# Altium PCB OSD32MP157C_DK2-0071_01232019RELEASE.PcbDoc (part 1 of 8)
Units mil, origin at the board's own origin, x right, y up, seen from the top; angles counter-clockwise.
Board outline 3976.38 x 2795.28 mil, 6 copper layers (Top Layer, Signal Layer 1, Signal Layer 2, Signal Layer 3, Signal Layer 4, Bottom Layer), stack 61.268 mil thick; 404 components, 418 nets, 1720 pads, 1233 vias.
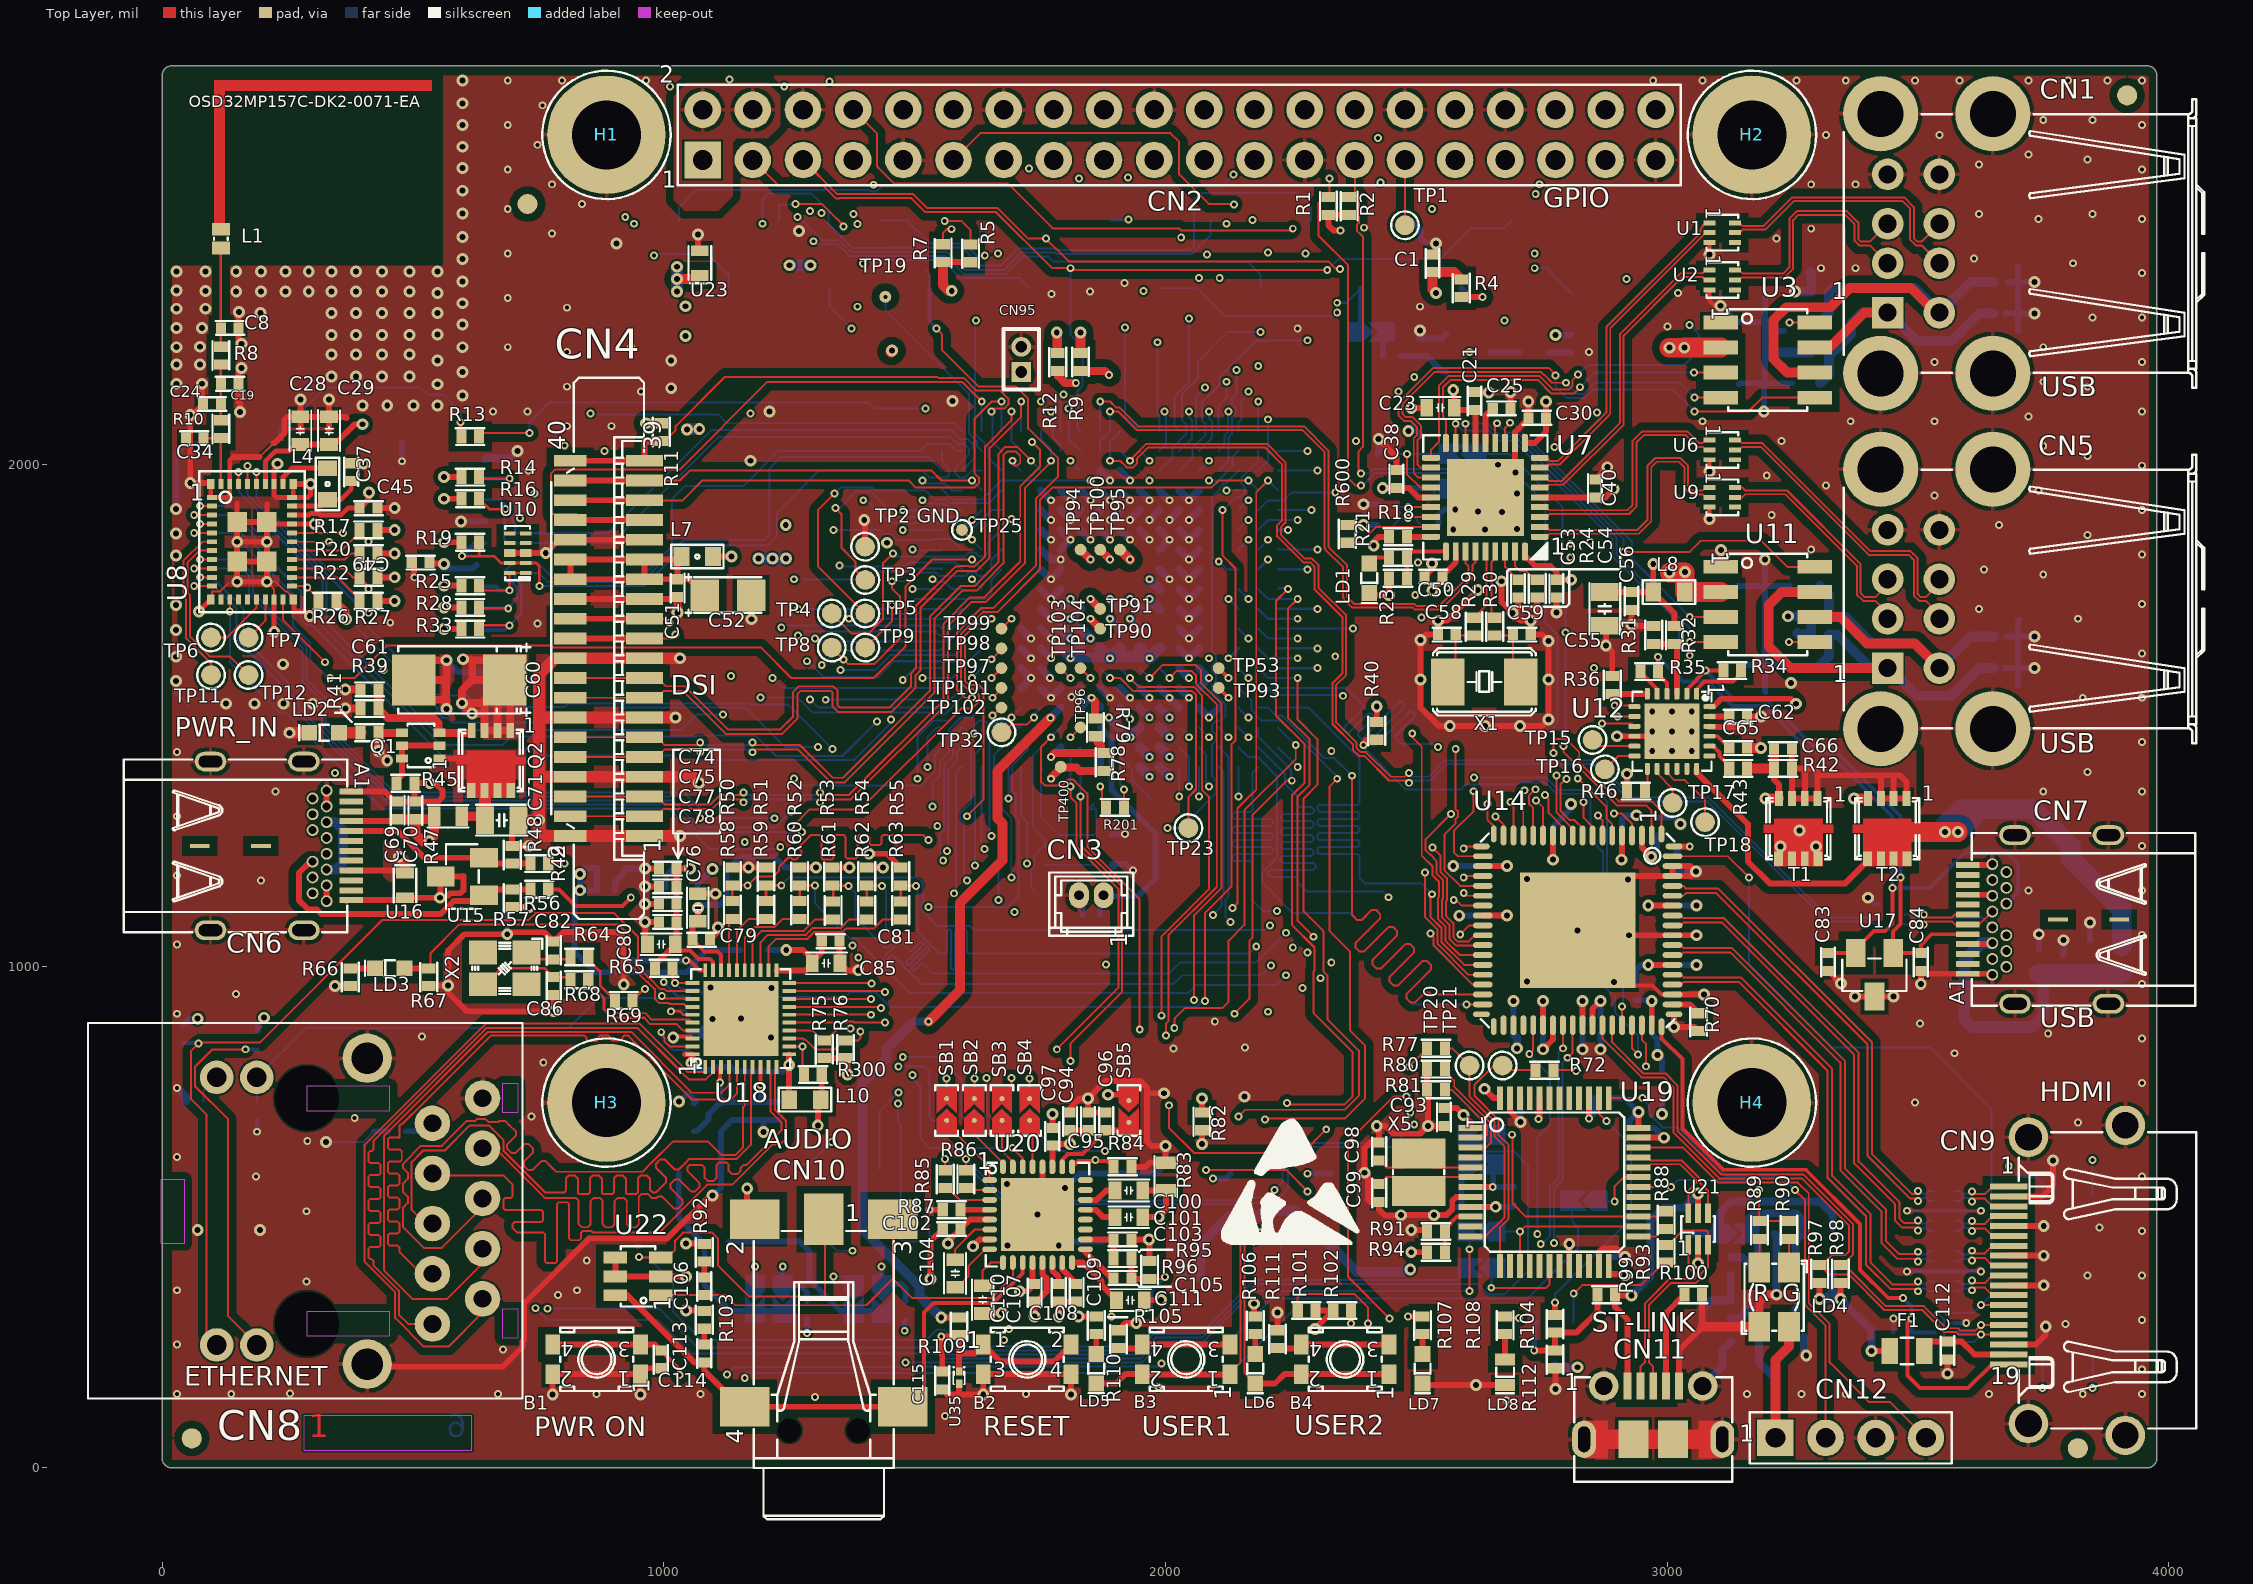
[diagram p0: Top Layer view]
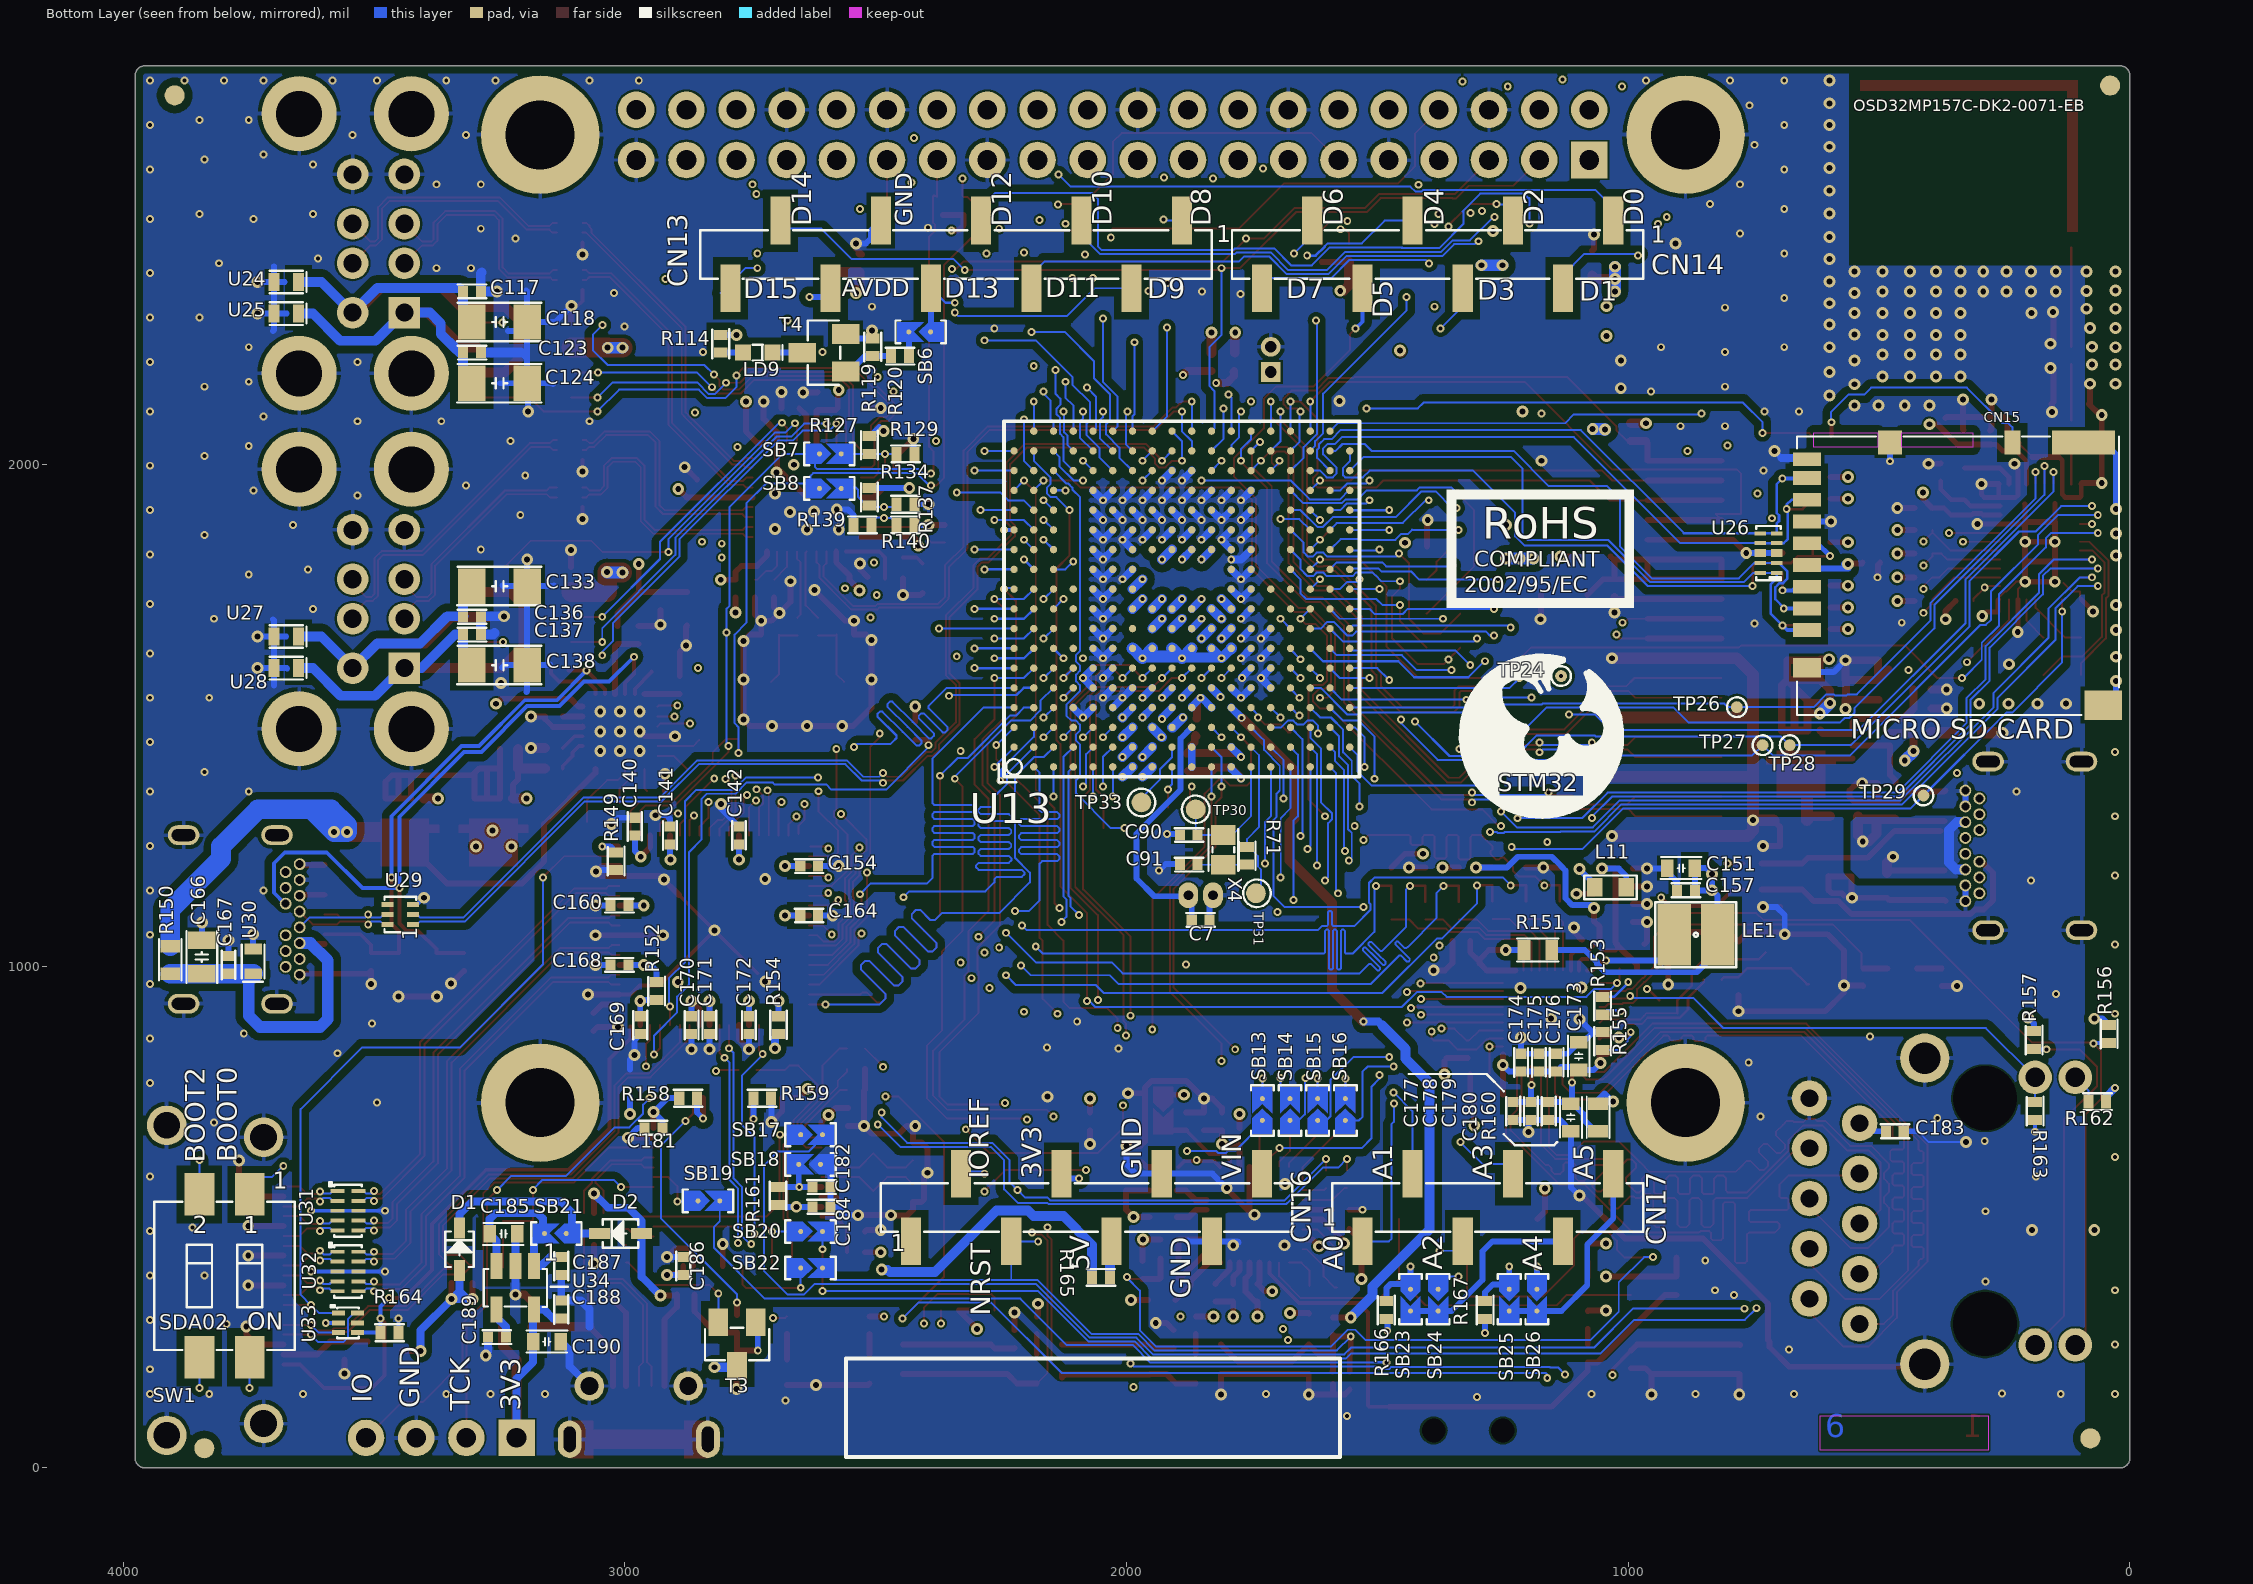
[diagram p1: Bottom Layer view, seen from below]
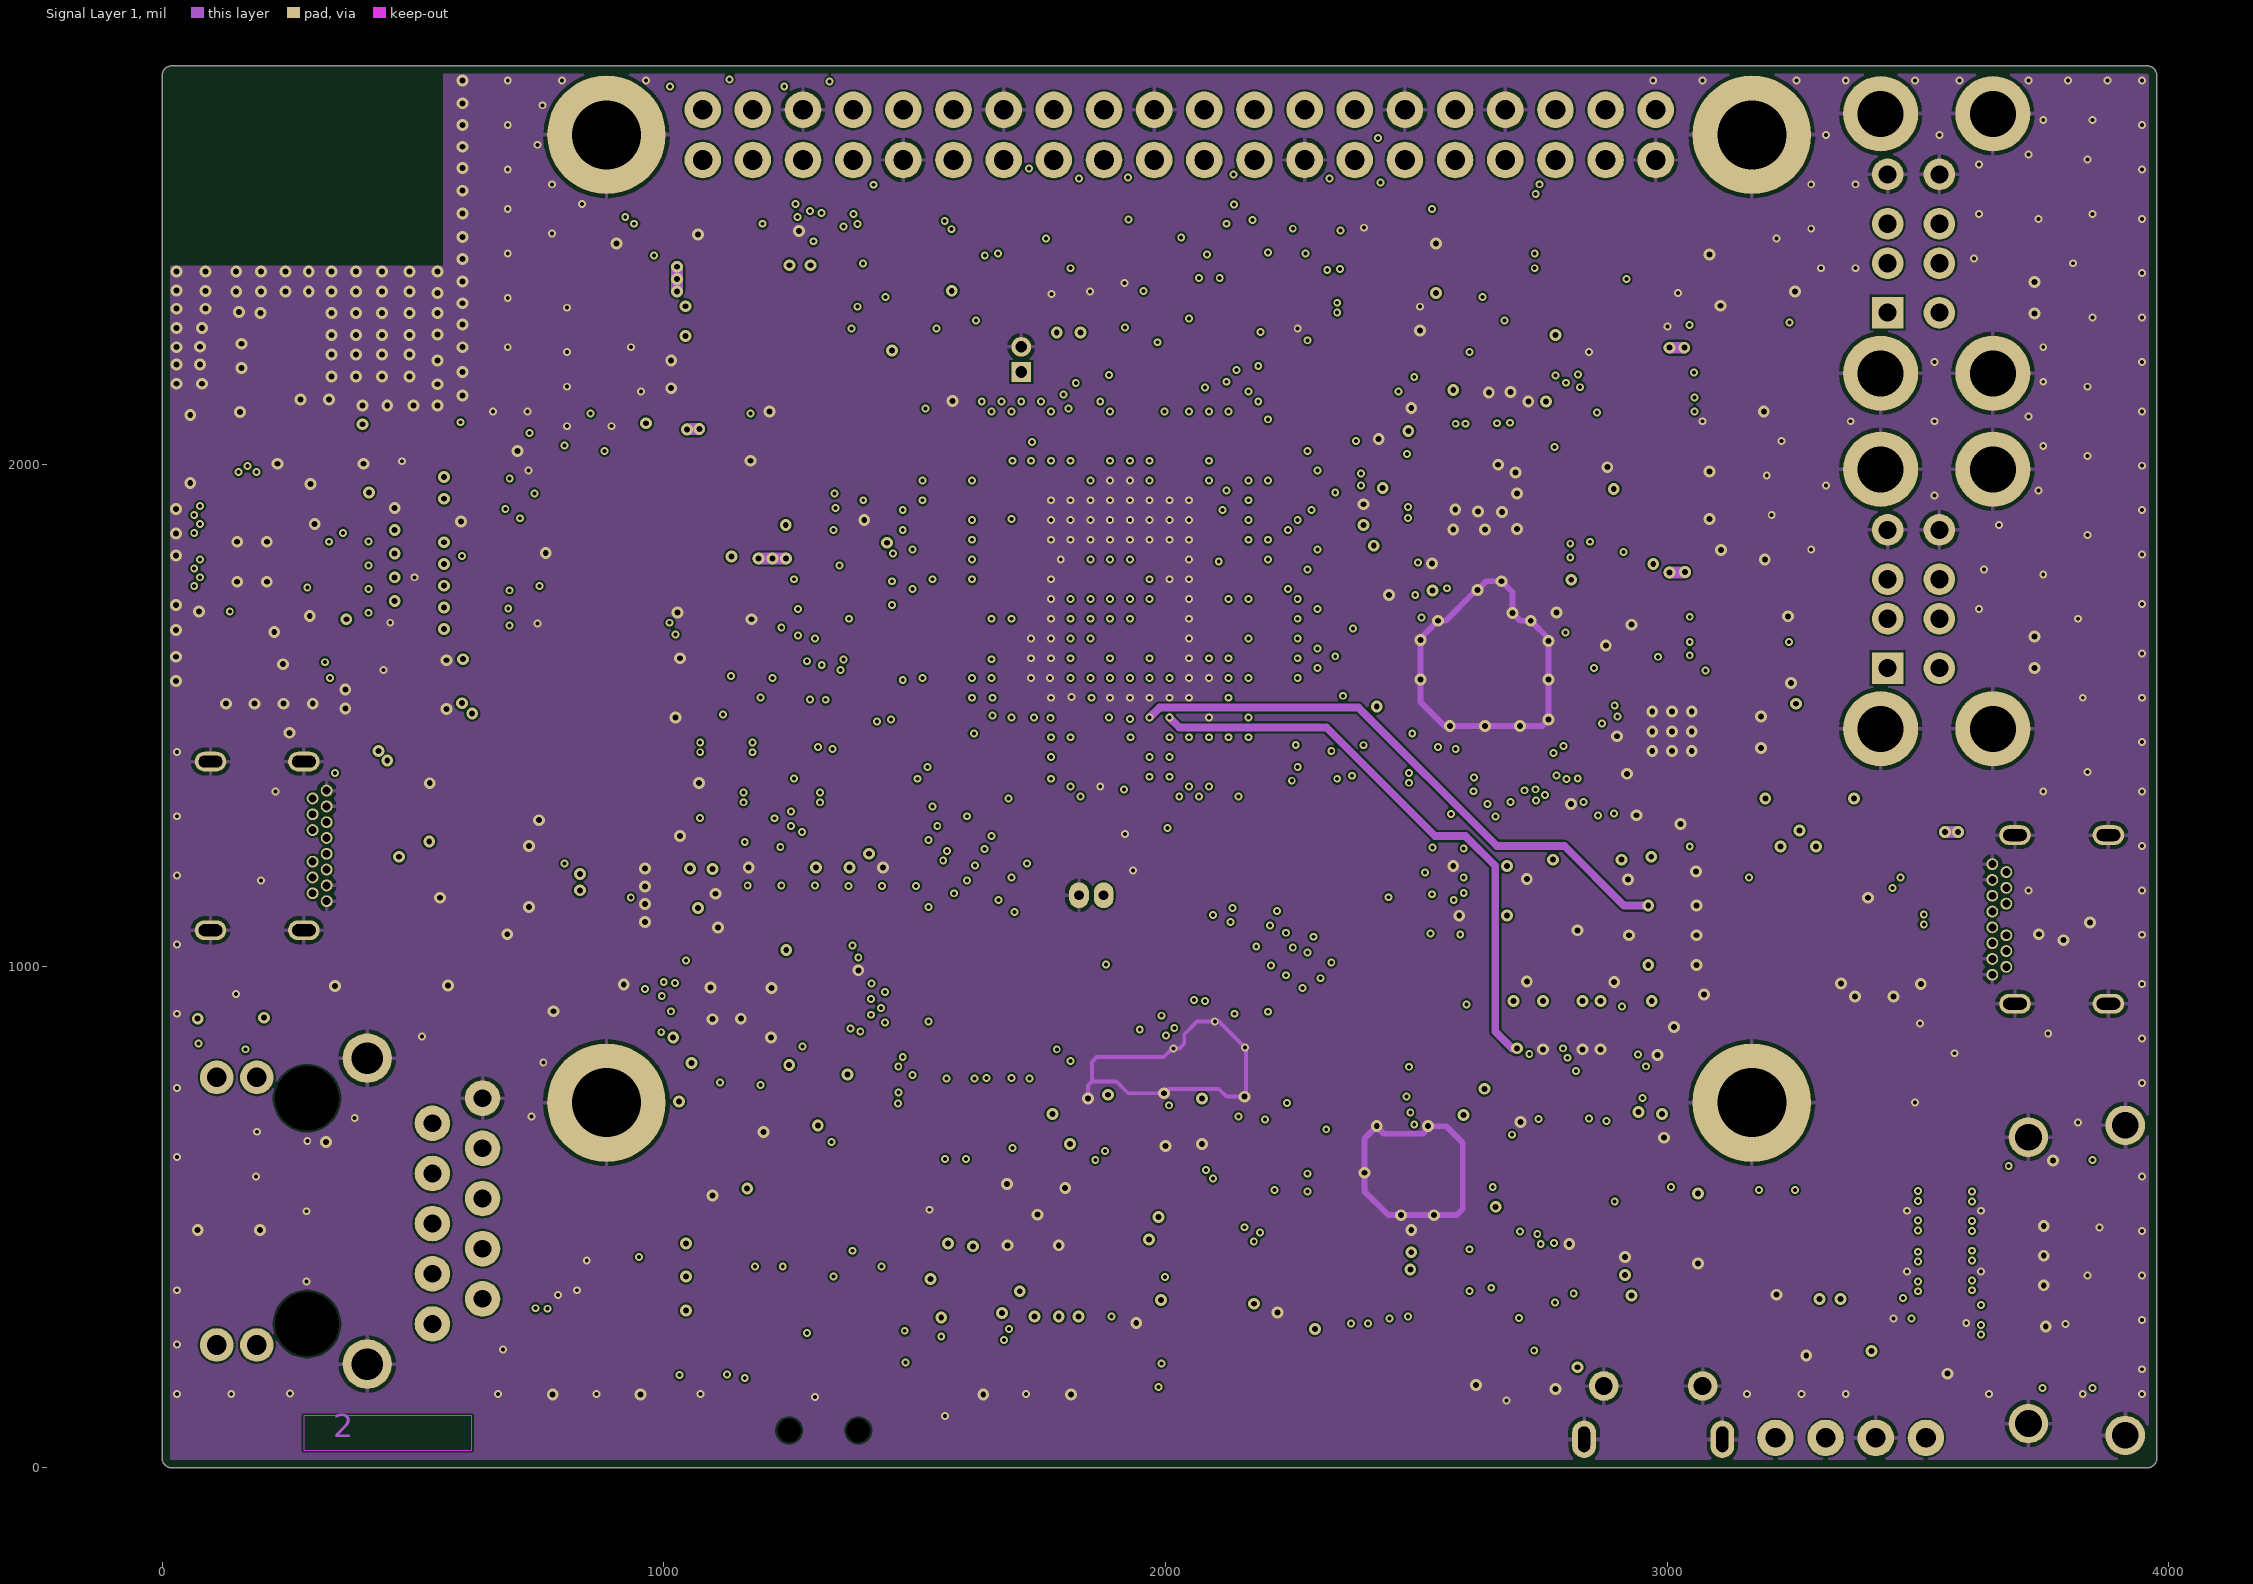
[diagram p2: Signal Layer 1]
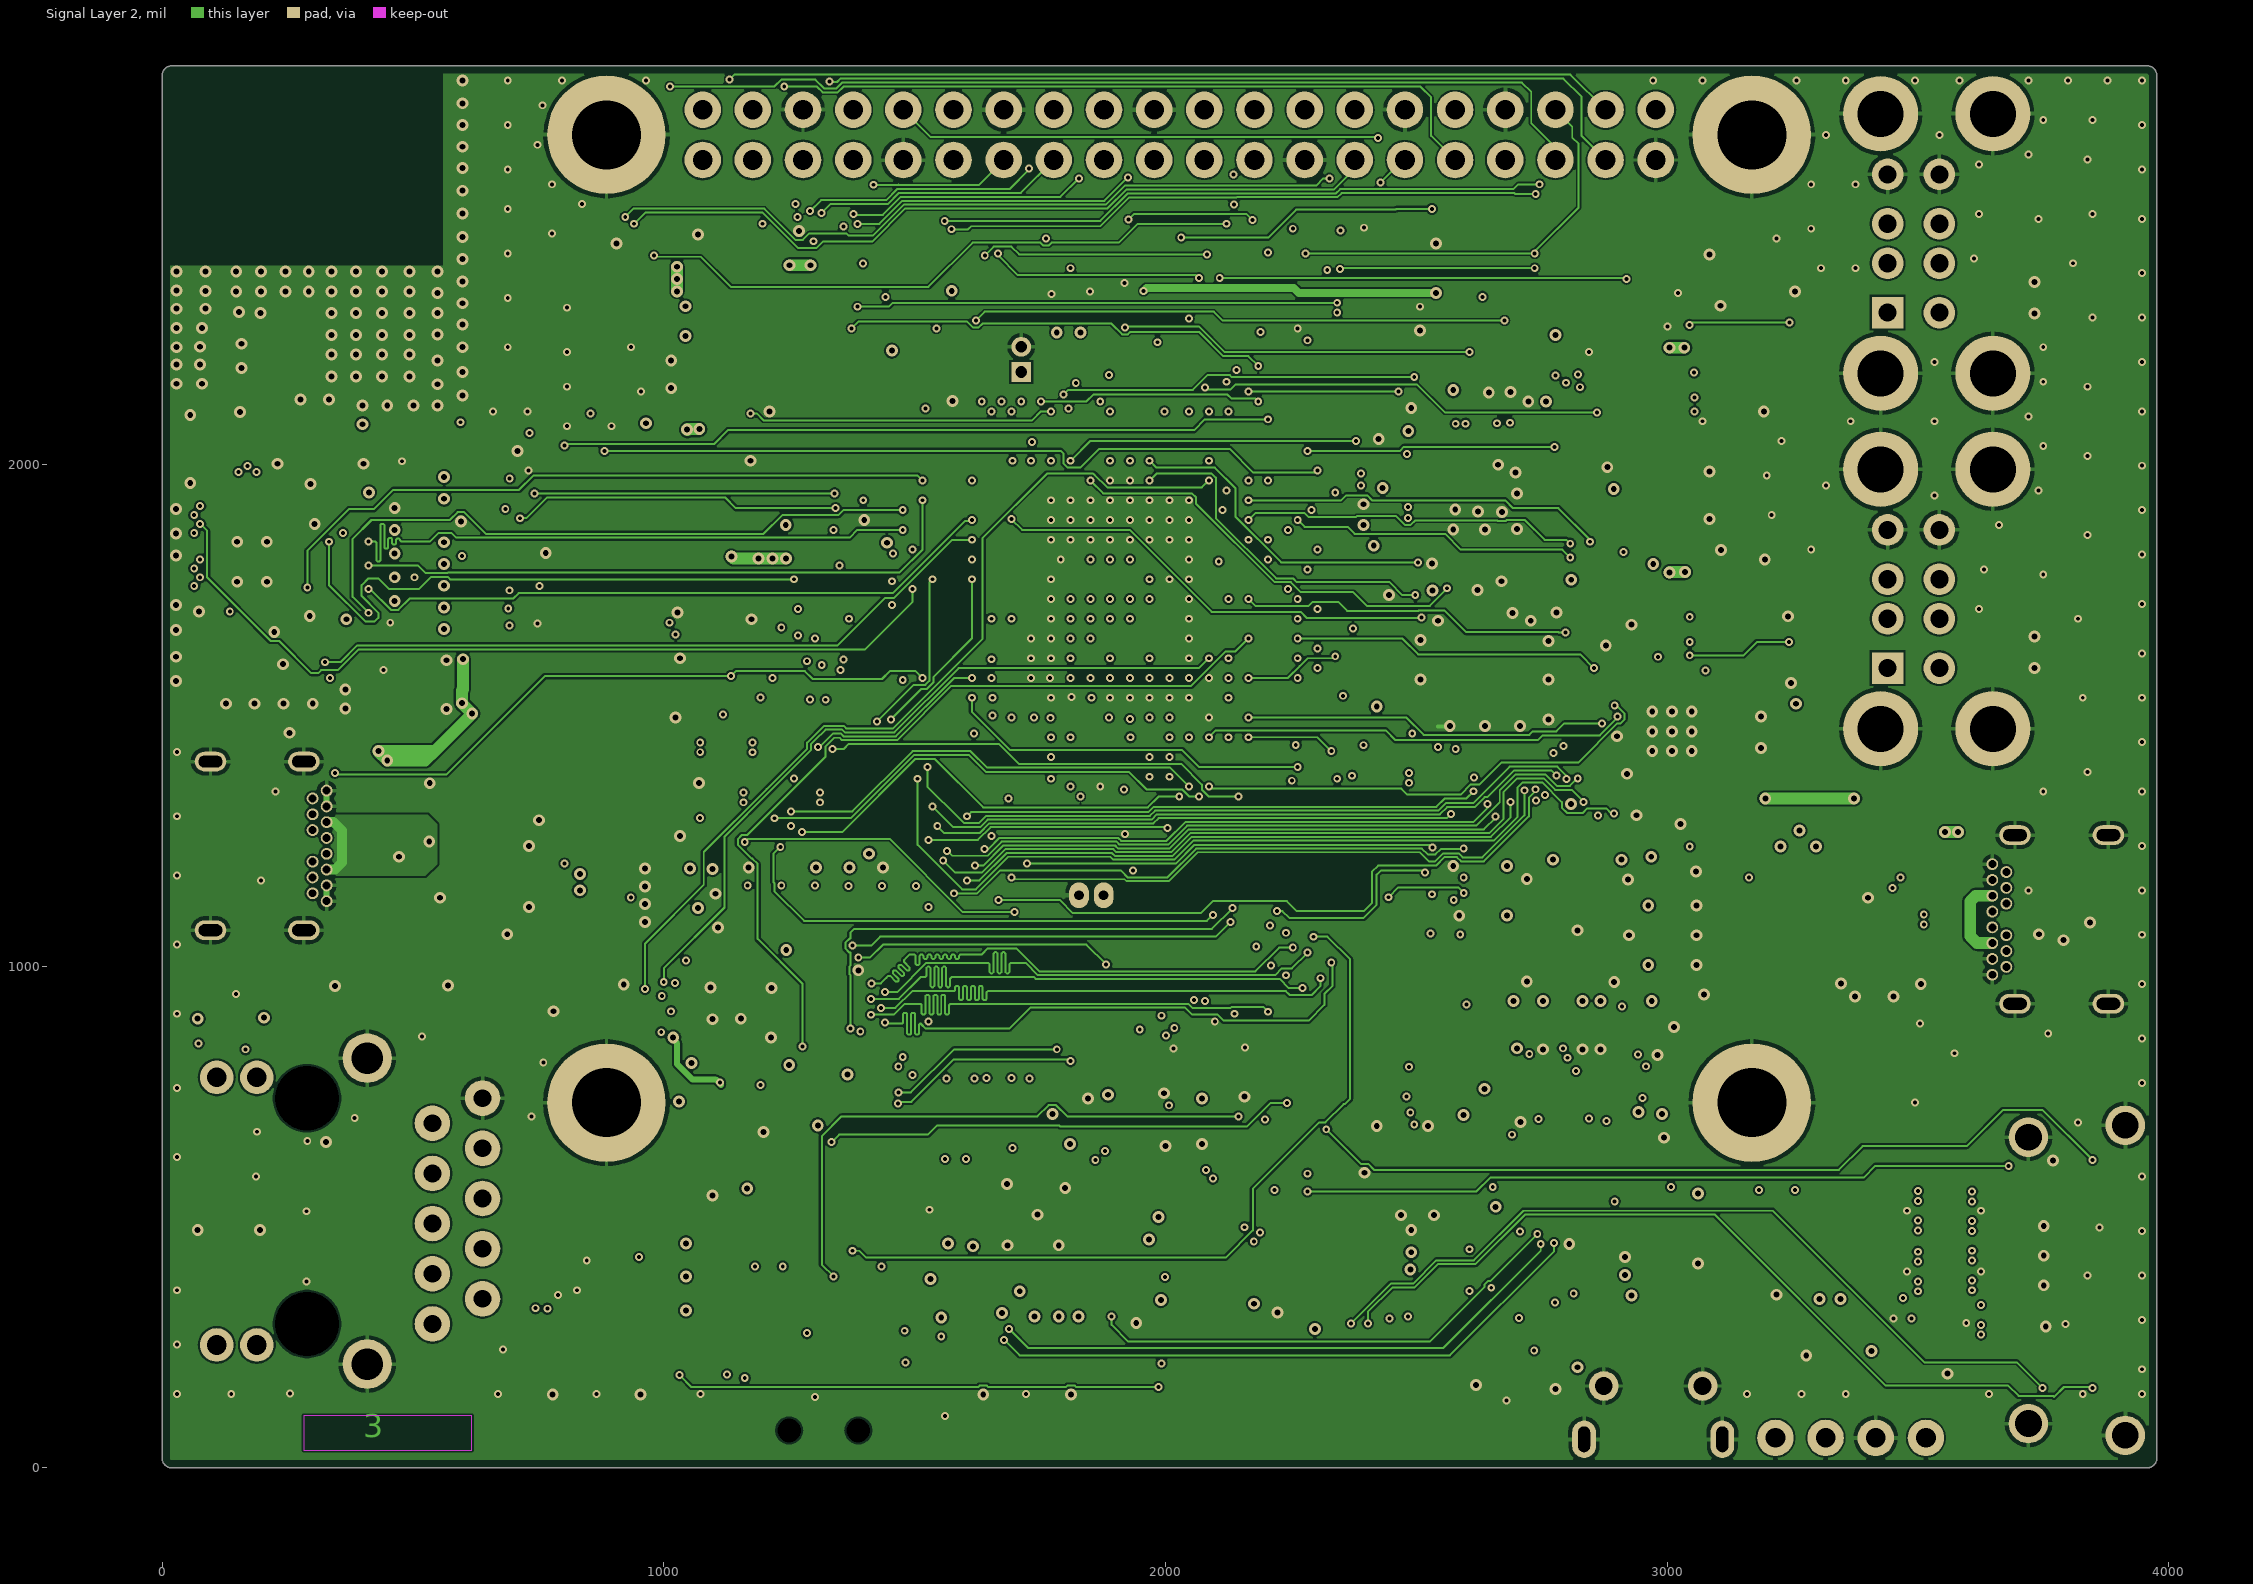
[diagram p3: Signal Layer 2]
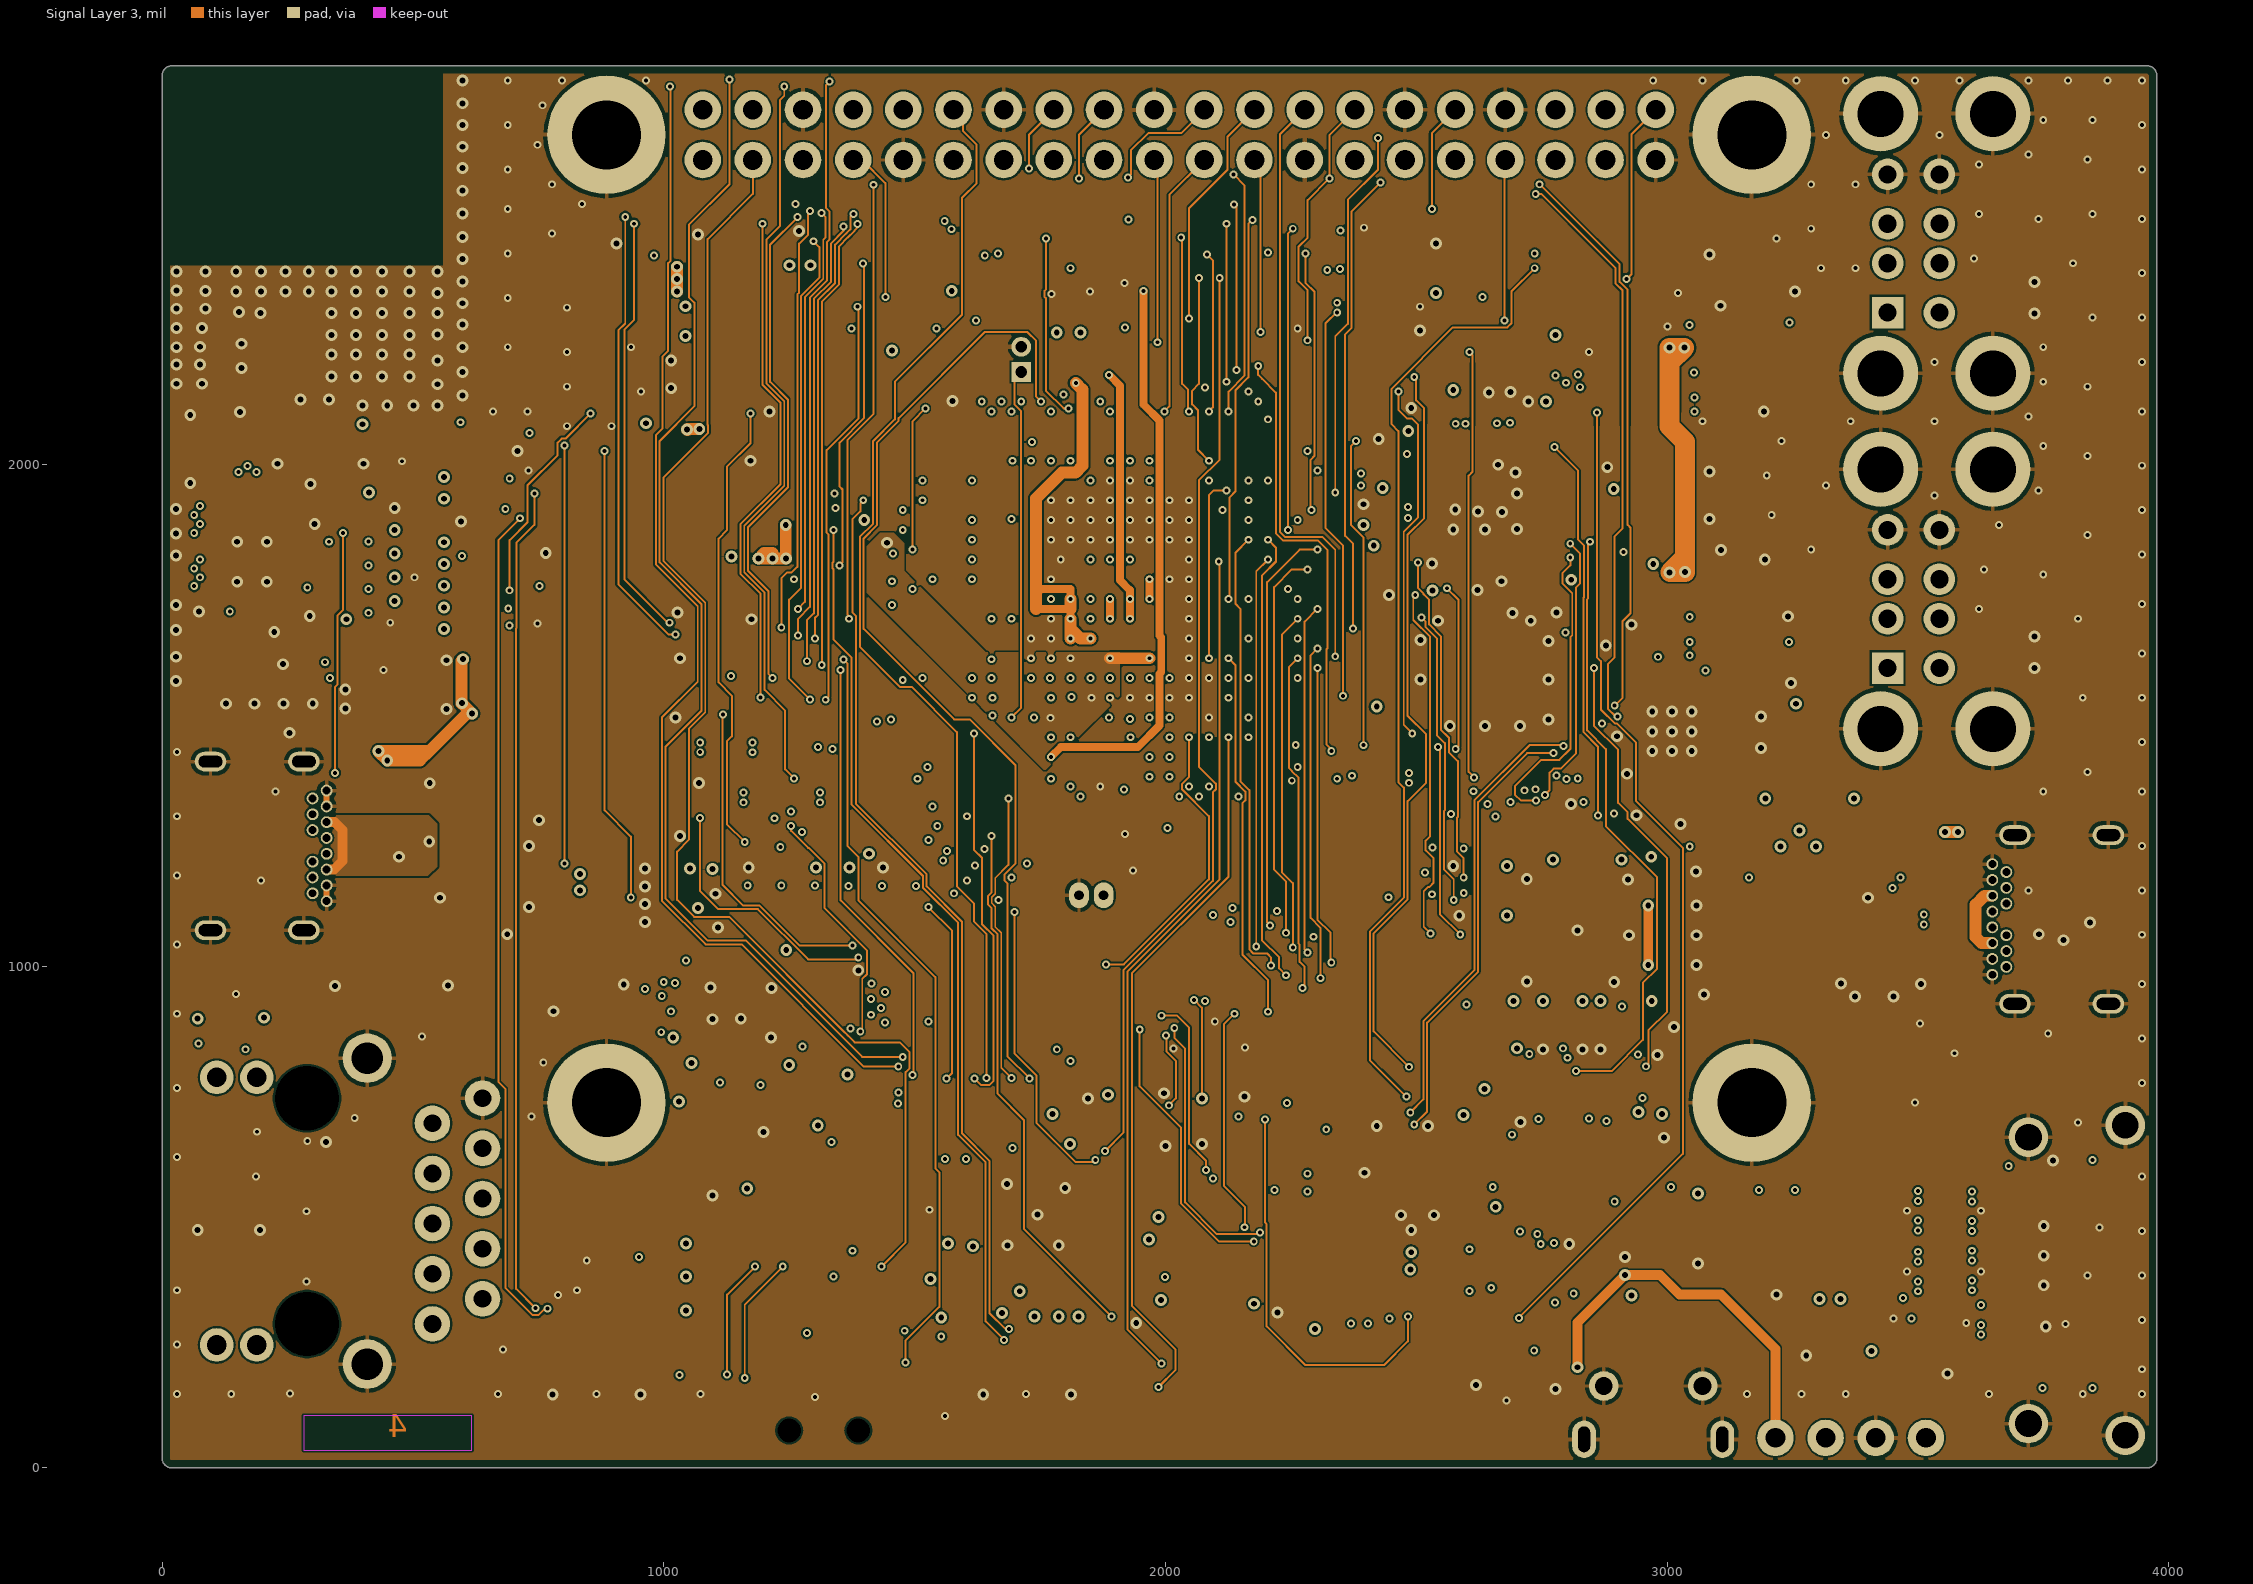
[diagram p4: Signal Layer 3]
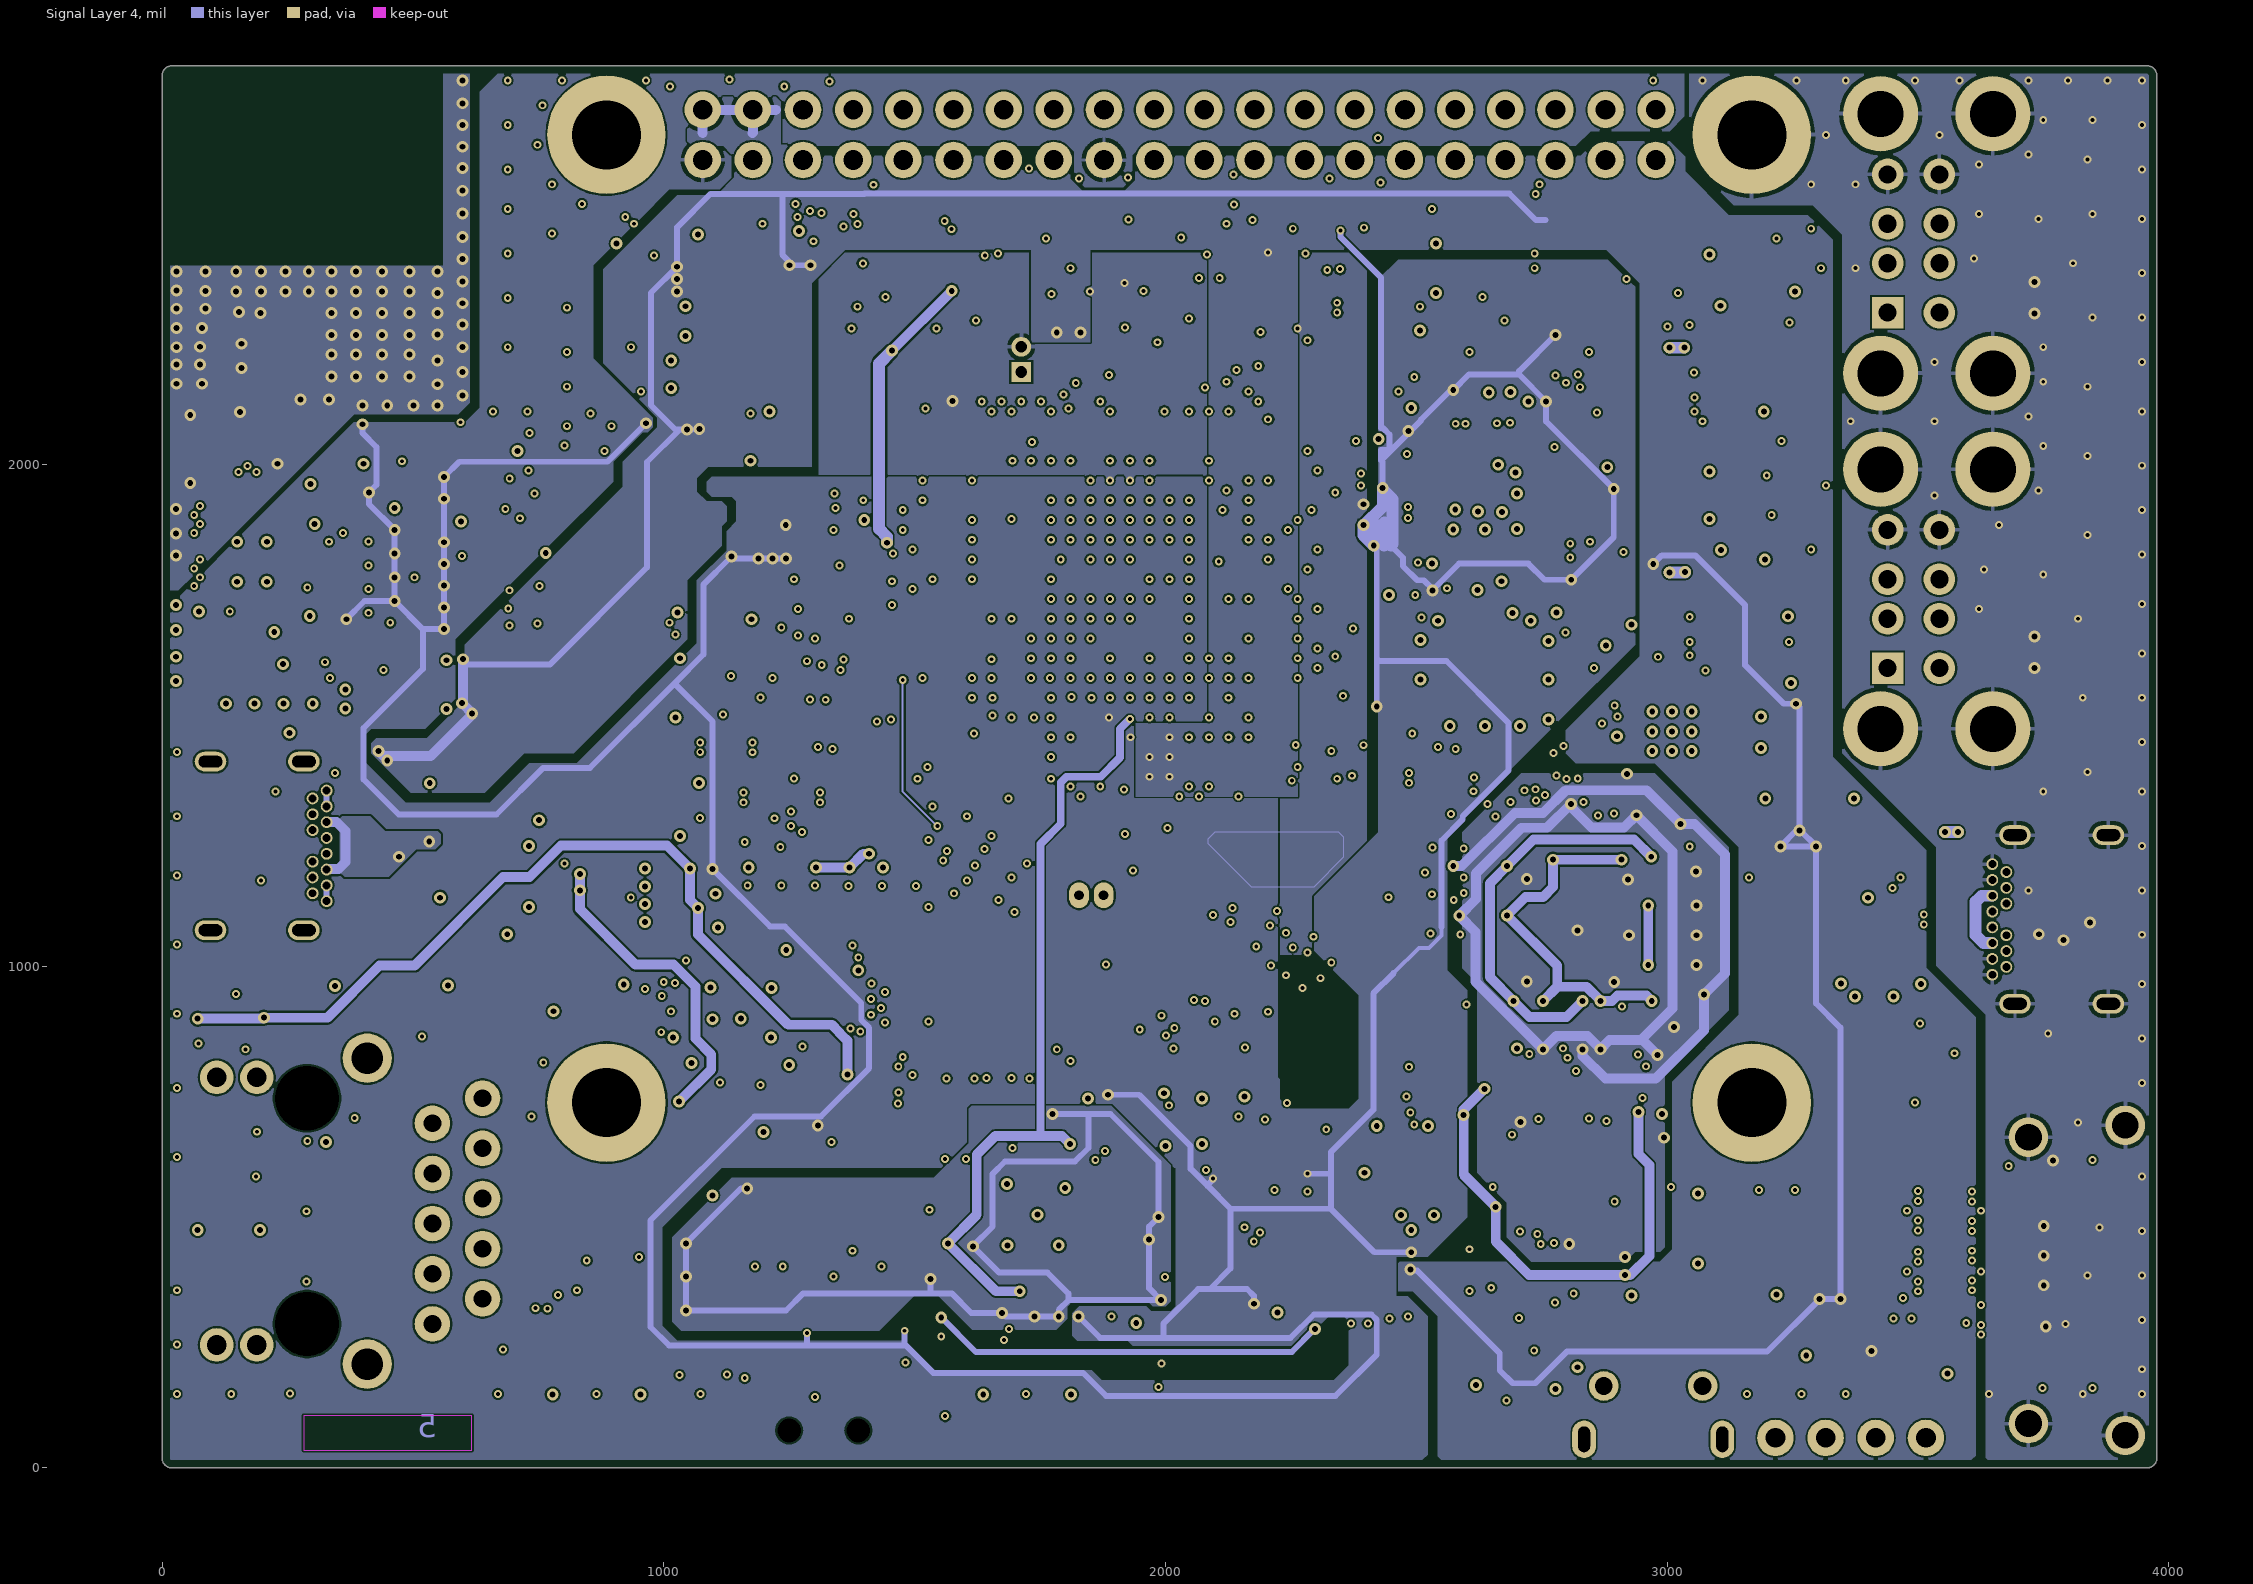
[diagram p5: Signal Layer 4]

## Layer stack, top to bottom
Top Solder: solder mask 0.8, Solder Resist, Dk 3.5
Top Layer: signal copper 1.4567
Dielectric 1: prepreg 3.8819, IT-180A 3313H, Dk 4.2
Signal Layer 1: signal copper 1.378
Dielectric 2: core 5.1181, IT-180A, Dk 4.2
Signal Layer 2: signal copper 1.378
Dielectric 3: core 34.8425, IT-180A 1080*2, Dk 4.25
Signal Layer 3: signal copper 1.378
Dielectric 4: core 5.1181, IT-180A, Dk 4.2
Signal Layer 4: signal copper 1.378
Dielectric 5: prepreg 3.8819, IT-180A 3313H, Dk 4.2
Bottom Layer: signal copper 1.4567
Bottom Solder: solder mask 0.8, Solder Resist, Dk 3.5

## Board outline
0,19.69 ccw(c19.68,19.69) 19.68,0 3956.69,0 ccw(c3956.69,19.69) 3976.38,19.69 3976.38,2775.59 ccw(c3956.69,2775.59) 3956.69,2795.28 19.68,2795.28 ccw(c19.68,2775.59) 0,2775.59

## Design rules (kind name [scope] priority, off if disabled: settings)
AssemblyTestpoint [All] p1: testpointundercomponent=TRUE minsize=0 maxsize=100 preferedsize=1574.8 minholesize=0 maxholesize=40 preferedholesize=7.87 testpointgrid=1 usegrid=FALSE gridtolerance=0.01 allowsidetop=TRUE allowsidebottom=TRUE
BoardOutlineClearance [All] p1: gap=15.75 ignorepadtopadclearanceinfootprint=FALSE
Clearance Clearance_BGA05 [InComponentClass('CC_BGA05')] p1: gap=3.94 ignorepadtopadclearanceinfootprint=TRUE except(3.54: Arc-Track Track-SMDPad; 5.91: Arc-Fill Track-Fill SMDPad-Fill THPad-Fill Via-Fill Fill-Fill; 7.87: Arc-THPad Track-THPad SMDPad-SMDPad SMDPad-THPad THPad-THPad)
Clearance Clearance_BUS_50R_RGMII_ETH_L1 [InNetClass('NC_BUS_50R_RGMII_ETH-ALL') vs OnLayer('Top Layer')] p2: gap=3.94 ignorepadtopadclearanceinfootprint=TRUE except(5.91: Arc-Fill Track-Fill SMDPad-Fill THPad-Fill Via-Fill Fill-Fill; 7.87: Arc-THPad Track-THPad SMDPad-SMDPad SMDPad-THPad THPad-THPad; 10.24: Track-Track; 15.35: Arc-Poly Track-Poly SMDPad-Poly THPad-Poly Via-Poly Fill-Poly Poly-Poly)
Clearance Clearance_BUS_50R_RGMII_ETH_L6 [InNetClass('NC_BUS_50R_RGMII_ETH-ALL') vs OnLayer('Bottom Layer')] p3: gap=3.94 ignorepadtopadclearanceinfootprint=TRUE except(5.91: Arc-Fill Track-Fill SMDPad-Fill THPad-Fill Via-Fill Fill-Fill; 7.87: Arc-THPad Track-THPad SMDPad-SMDPad SMDPad-THPad THPad-THPad; 10.24: Track-Track; 15.35: Arc-Poly Track-Poly SMDPad-Poly THPad-Poly Via-Poly Fill-Poly Poly-Poly)
Clearance Clearance_BUS_50R_RGMII_ETH_L3 [InNetClass('NC_BUS_50R_RGMII_ETH-ALL') vs OnLayer('Signal Layer 2')] p4: gap=3.94 ignorepadtopadclearanceinfootprint=TRUE except(5.91: Arc-Fill Track-Fill SMDPad-Fill THPad-Fill Via-Fill Fill-Fill; 7.87: Arc-THPad Track-THPad SMDPad-SMDPad SMDPad-THPad THPad-THPad; 10.24: Track-Track; 19.68: Arc-Poly Track-Poly SMDPad-Poly THPad-Poly Via-Poly Fill-Poly Poly-Poly)
Clearance Clearance_DIFFPAIR_100R_DSI [InNetClass('NC_DIFFPAIR_100R_DSI')] p5: gap=3.94 ignorepadtopadclearanceinfootprint=TRUE except(5.91: Arc-Fill Track-Fill SMDPad-Fill THPad-Fill Via-Fill Fill-Fill; 7.87: Arc-THPad Track-THPad SMDPad-SMDPad SMDPad-THPad THPad-THPad; 11.81: Arc-Poly Track-Poly SMDPad-Poly THPad-Poly Via-Poly Fill-Poly Poly-Poly)
Clearance Clearance_DIFFPAIR_100R_RGMII-RJ45 [InNetClass('NC_DIFFPAIR_100R_RGMII-RJ45')] p6: gap=3.94 ignorepadtopadclearanceinfootprint=TRUE except(5.91: Arc-Fill Track-Fill SMDPad-Fill THPad-Fill Via-Fill Fill-Fill; 7.87: Arc-THPad Track-THPad SMDPad-SMDPad SMDPad-THPad THPad-THPad; 11.81: Arc-Poly Track-Poly SMDPad-Poly THPad-Poly Via-Poly Fill-Poly Poly-Poly)
Clearance Clearance_DIFFPAIR_100R_HDMI-TX [InNetClass('NC_DIFFPAIR_100R_HDMI-TX')] p7: gap=3.94 ignorepadtopadclearanceinfootprint=TRUE except(5.91: Arc-Fill Track-Fill SMDPad-Fill THPad-Fill Via-Fill Fill-Fill; 7.87: Arc-THPad Track-THPad SMDPad-SMDPad SMDPad-THPad THPad-THPad; 11.81: Arc-Poly Track-Poly SMDPad-Poly THPad-Poly Via-Poly Fill-Poly Poly-Poly)
Clearance Clearance_DIFFPAIR_90R_USB [InNetClass('NC_DIFFPAIR_90R_USB')] p8: gap=3.94 ignorepadtopadclearanceinfootprint=TRUE except(3.54: Track-Track; 5.91: Arc-Fill Track-Fill SMDPad-Fill THPad-Fill Via-Fill Fill-Fill; 7.87: Arc-THPad Track-THPad SMDPad-SMDPad SMDPad-THPad THPad-THPad; 10.63: Arc-Poly Track-Poly SMDPad-Poly THPad-Poly Via-Poly Fill-Poly Poly-Poly)
Clearance Clearance_BUS_50R_SDMMC1 [InNetClass('NC_BUS_50R_SDMMC1') vs OnLayer('Bottom Layer')] p9: gap=3.94 ignorepadtopadclearanceinfootprint=TRUE except(5.91: Arc-Fill Track-Fill SMDPad-Fill THPad-Fill Via-Fill Fill-Fill; 7.87: Arc-THPad Track-THPad SMDPad-SMDPad SMDPad-THPad THPad-THPad; 10.24: Track-Track; 15.35: Arc-Poly Track-Poly SMDPad-Poly THPad-Poly Via-Poly Fill-Poly Poly-Poly)
Clearance Clearance_ANTENNA_50R_WIFI [InNetClass('NC_ANTENNA_50R_WIFI')] p10: gap=3.94 ignorepadtopadclearanceinfootprint=TRUE except(5.91: Arc-Fill Track-Fill SMDPad-Fill THPad-Fill Via-Fill Fill-Fill; 7.87: Arc-THPad Track-Track Track-SMDPad Track-THPad SMDPad-SMDPad SMDPad-THPad THPad-THPad; 15.35: Arc-Poly Track-Poly SMDPad-Poly THPad-Poly Via-Poly Fill-Poly Poly-Poly)
Clearance Clearance_BUS_50R_SDMMC1_CK [InNetClass('NC_BUS_50R_SDMMC1_CK') vs OnLayer('Signal Layer 2')] p11: gap=3.94 ignorepadtopadclearanceinfootprint=TRUE except(5.91: Arc-Fill Track-Fill SMDPad-Fill THPad-Fill Via-Fill Fill-Fill; 7.87: Arc-THPad Track-THPad SMDPad-SMDPad SMDPad-THPad THPad-THPad; 10.24: Track-Track; 29.53: Arc-Poly Track-Poly SMDPad-Poly THPad-Poly Via-Poly Fill-Poly Poly-Poly)
Clearance Clearance_1 [OnLayer('Top Layer') vs OnLayer('Top Layer')] p12: gap=3.94 ignorepadtopadclearanceinfootprint=TRUE except(3.54: Arc-Arc Arc-Track Track-Track; 15.35: Arc-Poly Track-Poly SMDPad-Poly THPad-Poly Via-Poly Fill-Poly Poly-Poly)
Clearance Clearance_6 [OnLayer('Bottom Layer') vs OnLayer('Bottom Layer')] p13: gap=3.94 ignorepadtopadclearanceinfootprint=TRUE except(3.54: Arc-Arc Arc-Track Track-Track; 15.35: Arc-Poly Track-Poly SMDPad-Poly THPad-Poly Via-Poly Fill-Poly Poly-Poly)
Clearance [All] p14: gap=3.94 ignorepadtopadclearanceinfootprint=TRUE except(3.54: Arc-Arc Arc-Track Track-Track)
ComponentClearance [All] p1 off: gap=0.98 collisioncheckmode=3 verticalgap=100000 showdistances=TRUE
DiffPairsRouting DiffPairsRouting_90R_USB [InDifferentialPairClass('DIFFPAIR_90R_USB')] p1: maxlimit=3.54 minlimit=3.54 mostfreqgap=3.54 toplayer_minwidth=3.54 toplayer_maxwidth=3.94 toplayer_prefwidth=3.94 midlayer1_minwidth=3.54 midlayer1_maxwidth=3.94 midlayer1_prefwidth=3.94 midlayer2_minwidth=3.54 midlayer2_maxwidth=3.94 midlayer2_prefwidth=3.94 midlayer3_minwidth=3.54 midlayer3_maxwidth=3.94 midlayer3_prefwidth=3.94 midlayer4_minwidth=3.54 midlayer4_maxwidth=3.94 midlayer4_prefwidth=3.94 bottomlayer_minwidth=3.54 bottomlayer_maxwidth=3.94 bottomlayer_prefwidth=3.94 maxuncoupledlength=500
DiffPairsRouting DiffPairsRouting_100R_DDR [InDifferentialPairClass('DIFFPAIR_100R_DDR')] p2: maxlimit=5.51 minlimit=5.12 mostfreqgap=5.51 toplayer_maxgap=5.12 toplayer_prefgap=5.12 toplayer_minwidth=3.54 toplayer_maxwidth=3.94 toplayer_prefwidth=3.94 midlayer1_maxgap=5.12 midlayer1_prefgap=5.12 midlayer1_minwidth=3.54 midlayer1_maxwidth=3.94 midlayer1_prefwidth=3.94 midlayer2_mingap=5.51 midlayer2_minwidth=3.54 midlayer2_maxwidth=3.54 midlayer2_prefwidth=3.54 midlayer3_maxgap=5.12 midlayer3_prefgap=5.12 midlayer3_minwidth=3.54 midlayer3_maxwidth=3.94 midlayer3_prefwidth=3.94 midlayer4_maxgap=5.12 midlayer4_prefgap=5.12 midlayer4_minwidth=3.54 midlayer4_maxwidth=3.94 midlayer4_prefwidth=3.94 bottomlayer_maxgap=5.12 bottomlayer_prefgap=5.12 bottomlayer_minwidth=3.54 bottomlayer_maxwidth=3.94 bottomlayer_prefwidth=3.94 maxuncoupledlength=500
DiffPairsRouting DiffPairsRouting_100R_HDMI-TX [InDifferentialPairClass('DIFFPAIR_100R_HDMI-TX')] p3: maxlimit=5.12 minlimit=5.12 mostfreqgap=5.12 toplayer_minwidth=3.54 toplayer_maxwidth=3.94 toplayer_prefwidth=3.94 midlayer1_minwidth=3.54 midlayer1_maxwidth=3.94 midlayer1_prefwidth=3.94 midlayer2_minwidth=3.54 midlayer2_maxwidth=3.94 midlayer2_prefwidth=3.94 midlayer3_minwidth=3.54 midlayer3_maxwidth=3.94 midlayer3_prefwidth=3.94 midlayer4_minwidth=3.54 midlayer4_maxwidth=3.94 midlayer4_prefwidth=3.94 bottomlayer_minwidth=3.54 bottomlayer_maxwidth=3.94 bottomlayer_prefwidth=3.94 maxuncoupledlength=500
DiffPairsRouting DiffPairsRouting_100R_DSI [InDifferentialPairClass('DIFFPAIR_100R_DSI')] p4: maxlimit=5.12 minlimit=5.12 mostfreqgap=5.12 toplayer_minwidth=3.54 toplayer_maxwidth=3.94 toplayer_prefwidth=3.94 midlayer1_minwidth=3.54 midlayer1_maxwidth=3.94 midlayer1_prefwidth=3.94 midlayer2_minwidth=3.54 midlayer2_maxwidth=3.94 midlayer2_prefwidth=3.94 midlayer3_minwidth=3.54 midlayer3_maxwidth=3.94 midlayer3_prefwidth=3.94 midlayer4_minwidth=3.54 midlayer4_maxwidth=3.94 midlayer4_prefwidth=3.94 bottomlayer_minwidth=3.54 bottomlayer_maxwidth=3.94 bottomlayer_prefwidth=3.94 maxuncoupledlength=500
DiffPairsRouting DiffPairsRouting_100R_RGMII-RJ45 [InDifferentialPairClass('DIFFPAIR_100R_RGMII-RJ45')] p5: maxlimit=5.12 minlimit=5.12 mostfreqgap=5.12 toplayer_minwidth=3.54 toplayer_maxwidth=3.94 toplayer_prefwidth=3.94 midlayer1_minwidth=3.54 midlayer1_maxwidth=3.94 midlayer1_prefwidth=3.94 midlayer2_minwidth=3.54 midlayer2_maxwidth=3.94 midlayer2_prefwidth=3.94 midlayer3_minwidth=3.54 midlayer3_maxwidth=3.94 midlayer3_prefwidth=3.94 midlayer4_minwidth=3.54 midlayer4_maxwidth=3.94 midlayer4_prefwidth=3.94 bottomlayer_minwidth=3.54 bottomlayer_maxwidth=3.94 bottomlayer_prefwidth=3.94 maxuncoupledlength=500
FabricationTestpoint [All] p1: side=3 testpointundercomponent=TRUE minsize=0 maxsize=100 preferedsize=60 minholesize=0 maxholesize=40 preferedholesize=32 testpointgrid=1 allowsidetop=TRUE allowsidebottom=TRUE usegrid=FALSE gridtolerance=0.01
FanoutControl Fanout_BGA [IsBGA] p1: bgadir=Out bgaviamode=Closest fanoutstyle=Auto fanoutdirection=Alternating viagrid=1 // Fanout_BGA (Default Rule)
FanoutControl Fanout_LCC [IsLCC] p2: bgadir=Out bgaviamode=Closest fanoutstyle=Auto fanoutdirection=Alternating viagrid=1 // Fanout_LCC (Default Rule)
FanoutControl Fanout_SOIC [IsSOIC] p3: bgadir=Out bgaviamode=Closest fanoutstyle=Auto fanoutdirection=Alternating viagrid=1 // Fanout_SOIC (Default Rule)
FanoutControl Fanout_Small [(CompPinCount < 5)] p4: bgadir=Out bgaviamode=Closest fanoutstyle=Auto fanoutdirection=OutThenIn viagrid=1 // Fanout_Small (Default Rule)
FanoutControl Fanout_Default [All] p5: bgadir=Out bgaviamode=Closest fanoutstyle=Auto fanoutdirection=Alternating viagrid=1 // Fanout_Default (Default Rule)
Height [All] p1 off: minheight=0 maxheight=3937.01 prefheight=19.68
HoleSize [All] p1: absolutevalues=TRUE maxlimit=393.7 minlimit=5.91 maxpercent=80.000 minpercent=20.000
HoleToHoleClearance [All] p1: gap=9.84 allowstackedmicrovias=TRUE
Length Length_BUS_50R_SDMMC1_ALL [InNetClass('NC_BUS_50R_SDMMC1_ALL')] p1: maxlimit=3937.01 minlimit=0
MatchedLengths MatchedLengths_BUS_50R_RGMII_ETH-ALL [InNetClass('NC_BUS_50R_RGMII_ETH-ALL')] p1: tolerance=39.37 checknetsindiffpair=FALSE checkdiffpairvsdiffpair=TRUE checkxsignals=TRUE checkothers=TRUE
MatchedLengths MatchedLengths_BUS_50R_SDMMC1_ALL [InNetClass('NC_BUS_50R_SDMMC1_ALL')] p2: tolerance=196.85 checknetsindiffpair=FALSE checkdiffpairvsdiffpair=TRUE checkxsignals=TRUE checkothers=TRUE
MatchedLengths MatchedLengths_DIFFPAIR_100R_DSI [InDifferentialPairClass('DIFFPAIR_100R_DSI')] p3: tolerance=196.85 checknetsindiffpair=FALSE checkdiffpairvsdiffpair=TRUE checkxsignals=TRUE checkothers=TRUE
MatchedLengths MatchedLengths_DIFFPAIR_100R_HDMI-TX_1-2 [InDifferentialPairClass('DIFFPAIR_100R_HDMI-TX_LENGTH_1-2')] p4: tolerance=157.48 checknetsindiffpair=FALSE checkdiffpairvsdiffpair=TRUE checkxsignals=TRUE checkothers=TRUE
MatchedLengths MatchedLengths_DIFFPAIR_100R_HDMI-TX_2-2 [InDifferentialPairClass('DIFFPAIR_100R_HDMI-TX_LENGTH_2-2')] p5: tolerance=157.48 checknetsindiffpair=FALSE checkdiffpairvsdiffpair=TRUE checkxsignals=TRUE checkothers=TRUE
MatchedLengths MatchedLengths_DIFFPAIR_90R_USB [InDifferentialPairClass('DIFFPAIR_90R_USB_LENGTH')] p6: tolerance=196.85 checknetsindiffpair=FALSE checkdiffpairvsdiffpair=TRUE checkxsignals=TRUE checkothers=TRUE
MinimumSolderMaskSliver [All] p1: minsoldermaskwidth=0
PlaneClearance [All] p1: clearance=23.62
PolygonConnect PolygonConnect_13 [All vs IsNamedPolygon('NETC66_2_L01_P093')] p1: connectstyle=Direct reliefconductorwidth=10 reliefentries=4 polygonreliefangle="90 Angle" airgapwidth=10
PolygonConnect PolygonConnect_12 [All vs IsNamedPolygon('NETC69_2_L01_P091')] p2: connectstyle=Direct reliefconductorwidth=10 reliefentries=4 polygonreliefangle="90 Angle" airgapwidth=10
PolygonConnect PolygonConnect_11 [All vs IsNamedPolygon('NETC71_2_L01_P088')] p3: connectstyle=Direct reliefconductorwidth=10 reliefentries=4 polygonreliefangle="90 Angle" airgapwidth=10
PolygonConnect PolygonConnect_10 [All vs IsNamedPolygon('5V_VIN_L01_P102')] p4: connectstyle=Direct reliefconductorwidth=10 reliefentries=4 polygonreliefangle="90 Angle" airgapwidth=10
PolygonConnect PolygonConnect_9 [All vs IsNamedPolygon('NETC195_2_L01_P093')] p5: connectstyle=Direct reliefconductorwidth=10 reliefentries=4 polygonreliefangle="90 Angle" airgapwidth=10
PolygonConnect PolygonConnect_8 [All vs IsNamedPolygon('5V_VIN_L01_P095')] p6: connectstyle=Direct reliefconductorwidth=10 reliefentries=4 polygonreliefangle="90 Angle" airgapwidth=10
PolygonConnect PolygonConnect_7 [All vs IsNamedPolygon('5V_VIN_L01_P020')] p7: connectstyle=Direct reliefconductorwidth=10 reliefentries=4 polygonreliefangle="90 Angle" airgapwidth=10
PolygonConnect PolygonConnect_6 [All vs IsNamedPolygon('NETC42_2_L01_P091')] p8: connectstyle=Direct reliefconductorwidth=10 reliefentries=4 polygonreliefangle="90 Angle" airgapwidth=10
PolygonConnect PolygonConnect_5 [All vs IsNamedPolygon('NETC44_2_L01_P088')] p9: connectstyle=Direct reliefconductorwidth=10 reliefentries=4 polygonreliefangle="90 Angle" airgapwidth=10
PolygonConnect PolygonConnect_4 [All vs IsNamedPolygon('NETC42_2_L01_P014')] p10: connectstyle=Direct reliefconductorwidth=10 reliefentries=4 polygonreliefangle="90 Angle" airgapwidth=10
PolygonConnect PolygonConnect_3 [All vs IsNamedPolygon('NETC42_2_L01_P078')] p11: connectstyle=Direct reliefconductorwidth=10 reliefentries=4 polygonreliefangle="90 Angle" airgapwidth=10
PolygonConnect PolygonConnect_2 [All vs IsNamedPolygon('GND_L01_P014')] p12: thpad.connectstyle=Relief thpad.reliefconductorwidth=11.81 thpad.reliefentries=4 thpad.polygonreliefangle="90 Angle" thpad.airgapwidth=7.87 smdpad.connectstyle=Relief smdpad.reliefconductorwidth=11.81 smdpad.reliefentries=4 smdpad.polygonreliefangle="90 Angle" smdpad.airgapwidth=7.87 via.connectstyle=Direct via.reliefconductorwidth=10 via.reliefentries=4 via.polygonreliefangle="90 Angle" via.airgapwidth=10
PolygonConnect PolygonConnect_1 [InNet('VTT_DDR')] p13: connectstyle=Direct reliefconductorwidth=10 reliefentries=4 polygonreliefangle="90 Angle" airgapwidth=10
PolygonConnect [All] p14: thpad.connectstyle=Relief thpad.reliefconductorwidth=7.87 thpad.reliefentries=4 thpad.polygonreliefangle="90 Angle" thpad.airgapwidth=7.87 smdpad.connectstyle=NoConnect smdpad.reliefconductorwidth=10 smdpad.reliefentries=4 smdpad.polygonreliefangle="90 Angle" smdpad.airgapwidth=7.87 via.connectstyle=Direct via.reliefconductorwidth=10 via.reliefentries=4 via.polygonreliefangle="90 Angle" via.airgapwidth=10
RoutingLayers RoutingLayers_BUS_50R_RGMII_ETH-ALL [InNetClass('NC_BUS_50R_RGMII_ETH-ALL')] p1: top layer_v5=TRUE mid layer 1_v5=TRUE mid layer 2_v5=TRUE mid layer 3_v5=TRUE mid layer 4_v5=TRUE bottom layer_v5=TRUE
RoutingLayers RoutingLayers_BUS_50R_SDMMC1_CK [InNetClass('NC_BUS_50R_SDMMC1_CK')] p2: top layer_v5=TRUE mid layer 1_v5=TRUE mid layer 2_v5=TRUE mid layer 3_v5=TRUE mid layer 4_v5=TRUE bottom layer_v5=TRUE
RoutingLayers RoutingLayers_BUS_50R_SDMMC1 [InNetClass('NC_BUS_50R_SDMMC1')] p3: top layer_v5=TRUE mid layer 1_v5=TRUE mid layer 2_v5=TRUE mid layer 3_v5=TRUE mid layer 4_v5=TRUE bottom layer_v5=TRUE
RoutingLayers RoutingLayers_ANTENNA_50R_WIFI [InNetClass('NC_ANTENNA_50R_WIFI')] p4: top layer_v5=TRUE mid layer 1_v5=TRUE mid layer 2_v5=TRUE mid layer 3_v5=TRUE mid layer 4_v5=TRUE bottom layer_v5=TRUE
RoutingLayers RoutingLayers_SINGLE_55R_DDR [InNetClass('NC_SINGLE_55R_DDR')] p5: top layer_v5=TRUE mid layer 1_v5=TRUE mid layer 2_v5=TRUE mid layer 3_v5=TRUE mid layer 4_v5=TRUE bottom layer_v5=TRUE
RoutingLayers RoutingLayers_DIFFPAIR_100R_DDR [InDifferentialPairClass('DIFFPAIR_100R_DDR')] p6: top layer_v5=TRUE mid layer 1_v5=TRUE mid layer 2_v5=TRUE mid layer 3_v5=TRUE mid layer 4_v5=TRUE bottom layer_v5=TRUE
RoutingLayers RoutingLayers_DIFFPAIR_100R_DSI [InDifferentialPairClass('DIFFPAIR_100R_DSI')] p7: top layer_v5=TRUE mid layer 1_v5=TRUE mid layer 2_v5=TRUE mid layer 3_v5=TRUE mid layer 4_v5=TRUE bottom layer_v5=TRUE
RoutingLayers RoutingLayers_DIFFPAIR_100R_RGMII-RJ45 [InDifferentialPairClass('DIFFPAIR_100R_RGMII-RJ45')] p8: top layer_v5=TRUE mid layer 1_v5=TRUE mid layer 2_v5=TRUE mid layer 3_v5=TRUE mid layer 4_v5=TRUE bottom layer_v5=TRUE
RoutingLayers RoutingLayers_DIFFPAIR_100R_HDMI-TX [InDifferentialPairClass('DIFFPAIR_100R_HDMI-TX')] p9: top layer_v5=TRUE mid layer 1_v5=TRUE mid layer 2_v5=TRUE mid layer 3_v5=TRUE mid layer 4_v5=TRUE bottom layer_v5=TRUE
RoutingLayers RoutingLayers_DIFFPAIR_90R_USB [InDifferentialPairClass('DIFFPAIR_90R_USB')] p10: top layer_v5=TRUE mid layer 1_v5=TRUE mid layer 2_v5=TRUE mid layer 3_v5=TRUE mid layer 4_v5=TRUE bottom layer_v5=TRUE
RoutingLayers [All] p11: top layer_v5=TRUE mid layer 1_v5=TRUE mid layer 2_v5=TRUE mid layer 3_v5=TRUE mid layer 4_v5=TRUE bottom layer_v5=TRUE
RoutingVias RoutingVias_Laser_L1-2 [InDrillLayerPair('Top Layer - Signal Layer 1')] p1: holewidth=3.94 width=9.84 viastyle="Through Hole" minholewidth=3.94 minwidth=9.84 maxholewidth=3.94 maxwidth=9.84
RoutingVias RoutingVias_GND [InNetClass('NC_GND')] p2: holewidth=11.81 width=23.62 viastyle="Through Hole" minholewidth=7.87 minwidth=15.75 maxholewidth=11.81 maxwidth=23.62
RoutingVias RoutingVias_ALIMS [InNetClass('NC_ALIMS')] p3: holewidth=11.81 width=23.62 viastyle="Through Hole" minholewidth=7.87 minwidth=15.75 maxholewidth=11.81 maxwidth=23.62
RoutingVias [All] p4: holewidth=7.87 width=15.75 viastyle="Through Hole" minholewidth=7.87 minwidth=15.75 maxholewidth=11.81 maxwidth=23.62
SilkToSilkClearance [All] p1: silktosilkclearance=0
SilkToSolderMaskClearance [IsPad] p1: minsilkscreentomaskgap=0 clearancetoexposedcopper=TRUE
SolderMaskExpansion [All] p1: expansion=1.97
Width Width_BGA05 [InComponentClass('CC_BGA05')] p1: maxlimit=3.54 minlimit=3.54 preferedwidth=3.54
Width Width_GND [InNetClass('NC_GND')] p2: maxlimit=393.7 minlimit=3.54 preferedwidth=11.81
Width Width_ALIMS [InNetClass('NC_ALIMS')] p3: maxlimit=393.7 minlimit=3.54 preferedwidth=11.81
Width Width_SINGLE_55R_DDR [InNetClass('NC_SINGLE_55R_DDR')] p4: maxlimit=393.7 minlimit=3.54 preferedwidth=5 toplayer_prefwidth=4.72 midlayer1_prefwidth=4.72 midlayer3_prefwidth=4.72 midlayer4_prefwidth=4.72 bottomlayer_prefwidth=4.72 minimp=50.000000 maximp=50.000000 favimp=50.000000
Width Width_BUS_50R_SDMMC1_CK [InNetClass('NC_BUS_50R_SDMMC1_CK')] p5: maxlimit=5.12 minlimit=3.54 preferedwidth=5.12
Width Width_BUS_50R_SDMMC1 [InNetClass('NC_BUS_50R_SDMMC1')] p6: maxlimit=393.7 minlimit=3.54 preferedwidth=5.12
Width Width_ANTENNA_50R_WIFI [InNetClass('NC_ANTENNA_50R_WIFI')] p7: maxlimit=5.12 minlimit=5.12 preferedwidth=5.12
Width Width_BUS_50R_RGMII_ETH-TX [InNetClass('NC_BUS_50R_RGMII_ETH-TX')] p8: maxlimit=393.7 minlimit=3.54 preferedwidth=5.12
Width Width_BUS_50R_RGMII_ETH-RX [InNetClass('NC_BUS_50R_RGMII_ETH-RX')] p9: maxlimit=393.7 minlimit=3.54 preferedwidth=5.12
Width Width_BUS_50R_RGMII_ETH-CLK [InNetClass('NC_BUS_50R_RGMII_ETH-CLK')] p10: maxlimit=393.7 minlimit=3.54 preferedwidth=5.12
Width [All] p11: maxlimit=393.7 minlimit=3.54 preferedwidth=3.94
13 further rules are at their usual default settings.

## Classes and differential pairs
net class SDMMC2_D[0..3]: SDMMC2_D0 SDMMC2_D1 SDMMC2_D2 SDMMC2_D3
net class ETH_RXD[0..3]: ETH_RXD0 ETH_RXD1 ETH_RXD2 ETH_RXD3
net class ETH_TXD[0..3]: ETH_TXD0 ETH_TXD1 ETH_TXD2 ETH_TXD3
net class SDMMC1_D[0..3]: SDMMC1_D0 SDMMC1_D1 SDMMC1_D2 SDMMC1_D3
net class LTDC_G[0..7]: LTDC_G0 LTDC_G1 LTDC_G2 LTDC_G3 LTDC_G4 LTDC_G5 LTDC_G6 LTDC_G7
component class "2 - OSD32MP157C_18x18": B1 C90 C91 C114 CN95 m R1 R2 R5 R7 R40 R71 R166 R167 R201 R300 SB1 SB2 SB3 SB4 SB13 SB14 SB15 SB16 TP1 TP2 TP3 TP4 TP5 TP8 TP9 TP19 TP23 TP30 TP31 TP32 TP33 TP53 TP90 TP91 TP93 TP96 TP103 TP104 U13 X4
component class "3 - Power_MPU": C7 CN3 R9 R12 R78 R79 TP94 TP95 TP97 TP98 TP99 TP100 TP101 TP102 TP400
component class "4 - PMIC": C60 C61 C69 C70 C71 CN6 LD2 Q1 Q2 R39 R41 R45 R47 R48 R49 R56 R57 U15 U16
component class "5 - USB_Host_Hub&TypeC_DRP": C21 C23 C25 C30 C38 C40 C50 C53 C54 C55 C56 C58 C59 C62 C65 C66 C83 C84 C117 C118 C123 C124 C133 C136 C137 C138 C166 C167 CN1 CN5 CN7 L8 LD1 R18 R21 R23 R24 R29 R30 R31 R32 R34 R35 R36 R42 R43 R46 R127 R129 R134 R137 R139 R140 R150 R600 SB7 SB8 T1 T2 TP15 TP16 TP17 TP18 U1 U2 U3 U6 U7 U9 U11 U12 U17 U24 U25 U27 U28 U29 U30 X1
component class "6 - AUDIO": C94 C95 C96 C97 C100 C101 C102 C103 C104 C105 C106 C107 C108 C109 C110 C111 C113 CN10 R83 R84 R85 R86 R87 R92 R95 R96 R103 SB5 U20 U22
component class "7 - DSI_LCD": C51 C52 CN4 H1 H2 H3 H4 L7 R11
component class "8 - HDMI": C112 C140 C141 C142 C154 C160 C164 C168 C169 C170 C171 C172 CN9 F1 R70 R97 R98 R149 R152 R154 R164 U14 U31 U32 U33
component class "9 - GPIO_&_Arduino_ Connectors": C1 CN2 CN13 CN14 CN16 CN17 LD9 R4 R114 R119 R120 R165 SB6 SB23 SB24 SB25 SB26 T4 U23
component class "11 - Ethernet": C74 C75 C76 C77 C78 C79 C80 C81 C82 C85 C86 C151 C157 C173 C174 C175 C176 C177 C178 C179 C180 C183 CN8 L10 L11 LD3 LE1 R50 R51 R52 R53 R54 R55 R58 R59 R60 R61 R62 R63 R64 R65 R66 R67 R68 R69 R75 R76 R151 R153 R155 R156 R157 R160 R162 R163 U18 X2
component class "12 -  Peripherals": B2 B3 B4 C49 C115 CN15 HW1300 HW1301 HW1302 HW1303 LD5 LD6 LD7 LD8 R13 R14 R16 R19 R25 R28 R33 R82 R101 R102 R105 R106 R107 R108 R109 R110 R111 SW1 U10 U26 U35
component class "13 - WLAN_BLUETOOTH": C8 C19 C24 C28 C29 C34 C37 C45 CN18 L1 L4 R8 R10 R17 R20 R22 R26 R27 TP6 TP7 TP11 TP12 TP24 TP25 TP26 TP27 TP28 TP29 U8
component class "14 -ST_LINK_V2-1": C93 C98 C99 C181 C182 C184 C185 C186 C187 C188 C189 C190 CN11 CN12 D1 D2 LD4 R72 R77 R80 R81 R88 R89 R90 R91 R93 R94 R99 R100 R104 R112 R158 R159 R161 SB17 SB18 SB19 SB20 SB21 SB22 T3 TP20 TP21 U19 U21 U34 X5
net class ARD_A[0..5]: ARD_A0 ARD_A1 ARD_A2 ARD_A3 ARD_A4 ARD_A5
net class ARD_D[0..15]: ARD_D0 ARD_D1 ARD_D2 ARD_D3 ARD_D4 ARD_D5 ARD_D6 ARD_D7 ARD_D8 ARD_D9 ARD_D10 ARD_D11 ARD_D12 ARD_D13 ARD_D14 ARD_D15
net class BOOT[0..2]: BOOT0 BOOT1 BOOT2
net class LTDC_B[0..7]: LTDC_B0 LTDC_B1 LTDC_B2 LTDC_B3 LTDC_B4 LTDC_B5 LTDC_B6 LTDC_B7
net class LTDC_R[0..7]: LTDC_R0 LTDC_R1 LTDC_R2 LTDC_R3 LTDC_R4 LTDC_R5 LTDC_R6 LTDC_R7
differential pair DSI_CK: +DSI_CK_P -DSI_CK_N
differential pair DSI_D0: +DSI_D0_P -DSI_D0_N
differential pair DSI_D1: +DSI_D1_P -DSI_D1_N
differential pair USB1: +USB1_P -USB1_N
differential pair USB2: +USB2_P -USB2_N
differential pair RJ45_D1: +RJ45_D1_P -RJ45_D1_N
differential pair RJ45_D2: +RJ45_D2_P -RJ45_D2_N
differential pair RJ45_D3: +RJ45_D3_P -RJ45_D3_N
differential pair RJ45_D4: +RJ45_D4_P -RJ45_D4_N
differential pair TX0C: +TX0C_P -TX0C_N
differential pair TX0: +TX0_P -TX0_N
differential pair TX1C: +TX1C_P -TX1C_N
differential pair TX1: +TX1_P -TX1_N
differential pair TX2C: +TX2C_P -TX2C_N
differential pair TX2: +TX2_P -TX2_N
differential pair TXCC: +TXCC_P -TXCC_N
differential pair TXC: +TXC_P -TXC_N
differential pair USB1CN25: +USB1CN25_P -USB1CN25_N
differential pair USB2CN25: +USB2CN25_P -USB2CN25_N
differential pair USB3CN26: +USB3CN26_P -USB3CN26_N
differential pair USB4CN26: +USB4CN26_P -USB4CN26_N
differential pair USB_DCONN: +USB_DCONN_P -USB_DCONN_N
differential pair USB_STLK: +USB_STLK_P -USB_STLK_N
differential pair USBDN1: +USBDN1_P -USBDN1_N
differential pair USBDN2: +USBDN2_P -USBDN2_N
differential pair USBDN3: +USBDN3_P -USBDN3_N
differential pair USBDN4: +USBDN4_P -USBDN4_N

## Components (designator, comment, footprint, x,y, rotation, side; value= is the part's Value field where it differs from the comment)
B1 "" SWI_JIUBABA_C-TS-02H-2-5-B-V-T_R_BLUE 866.14,216.54 r180 top locked value=SW-PUSH-TS-02H-Blue
B2 "" SWI_JIUBABA_C-TS-02H-2-5-K-V-T_R_BLACK 1724.41,216.54 r0 top locked value=SW-PUSH-TS-02H-Black
B3 "SW-PUSH-TS-02H-Blue" SWI_JIUBABA_C-TS-02H-2-5-B-V-T_R_BLUE 2041.34,216.54 r180 top
B4 "SW-PUSH-TS-02H-Blue" SWI_JIUBABA_C-TS-02H-2-5-B-V-T_R_BLUE 2358.27,216.54 r180 top locked
C1 "" C0402 2532.48,2401.57 r270 top value=100nF
C7 "" C0402 1852.36,1092.52 r0 bottom value=100nF
C8 "Capacitor" C0402 134.84,2272.64 r180 top value=12pF
C19 "Capacitor" C0402 134.84,2161.42 r180 top value=12pF
C21 "Capacitor" C0402 2616.14,2126.97 r270 top value=100nF
C23 "Capacitor" C0603 2548.23,2113.19 r0 top value=4.7uF
C24 "Capacitor" C0402 99.41,2121.06 r0 top value=12pF
C25 "Capacitor" C0402 2670.28,2112.2 r180 top value=100nF
C28 "Capacitor" C0603 275.59,2067.91 r270 top value=2.2uF
C29 "Capacitor" C0603 332.68,2067.91 r270 top value=10uF
C30 "Capacitor" C0402 2741.14,2093.5 r0 top value=100nF
C34 "Capacitor" C0402 64.96,2053.15 r0 top value=12pF
C37 "" C0402 376.97,1985.24 r270 top value=4.7uF
C38 "Capacitor" C0402 2460.63,1971.46 r270 top value=100nF
C40 "Capacitor" C0402 2856.3,1952.76 r270 top value=100nF
C45 "" C0402 411.42,1913.39 r180 top value=100nF
C49 "" C0402 515.35,1804.77 r180 top value=4.7uF
C50 "Capacitor" C0402 2534.45,1776.57 r0 top value=100nF
C51 "" C0402 1027.56,1753.94 r90 top value=100nF
C52 "" CPOL_TAJ-A_1206_H180 1127.95,1740.16 r0 top value=10uF
C53 "Capacitor" C0402 2702.76,1752.95 r90 top value=100nF
C54 "Capacitor" C0402 2779.53,1752.95 r90 top value=100nF
C55 "Capacitor" C0805 2875.98,1712.6 r90 top value=47uF
C56 "Capacitor" C0402 2929.13,1728.35 r90 top value=100nF
C58 "Capacitor" C0402 2561.02,1661.42 r0 top value=18pF
C59 "Capacitor" C0402 2710.63,1661.42 r180 top value=18pF
C60 "Cap_POL_TANA" CPOL_TAJ-C_2312_H2P6 592.52,1570.87 r180 top locked value=47uF
C61 "" C0402 413.39,1552.17 r180 top value=100nF
C62 "Capacitor" C0402 3141.73,1498.03 r180 top value=1uF
C65 "Capacitor" C0402 3141.73,1435.04 r180 top value=1uF
C66 "Capacitor" C0402 3231.3,1433.07 r0 top value=100nF
C69 "Capacitor" C0402 469.49,1311.02 r270 top value=100pF
C70 "" C0402 504.92,1311.02 r90 top value=100nF
C71 "Capacitor" C0805 677.17,1291.34 r180 top value=10uF
C74 "" C0402 1007.87,1194.88 r0 top value=100nF
C75 "" C0402 1007.87,1159.45 r0 top value=100nF
C76 "" C0603 1067.91,1117.13 r90 top value=22uF
C77 "" C0402 1007.87,1124.02 r0 top value=100nF
C78 "" C0402 1007.87,1088.58 r0 top value=100nF
C79 "" C0402 1074.8,1053.15 r180 top value=100nF
C80 "" C0603 995.08,1044.29 r0 top value=22uF
C81 "" C0402 1332.68,1050.2 r180 top value=100nF
C82 "" C0402 780.51,1031.5 r270 top value=10pF
C83 "Capacitor" C0402 3320.87,1008.86 r90 top value=470pF
C84 "Capacitor" C0402 3505.91,1008.86 r90 top value=470pF
C85 "" C0603 1323.82,1005.91 r180 top value=22uF
C86 "" C0402 780.51,960.63 r90 top value=10pF
C90 "Capacitor" C0402 1875.98,1261.81 r0 bottom value=12pF
C91 "Capacitor" C0402 1875.98,1202.76 r0 bottom value=12pF
C93 "" C0402 2555.12,699.8 r90 top value=100nF
C94 "" C0402 1810.04,690.94 r270 top value=1uF
C95 "" C0402 1845.47,690.94 r270 top value=100nF
C96 "" C0402 1881.89,690.94 r90 top value=100nF
C97 "" C0402 1774.61,660.43 r270 top value=100nF
C98 "" C0402 2426.18,630.91 r90 top value=10pF
C99 "" C0402 2426.18,548.23 r270 top value=10pF
C100 "" C0603 1927.17,553.15 r180 top value=150pF
C101 "" C0603 1927.17,500 r180 top value=150pF
C102 "" C0402 1573.82,476.38 r0 top value=1uF
C103 "" C0402 1914.37,455.71 r180 top value=100nF
C104 "" C0603 1580.71,387.8 r90 top value=1uF
C105 "" C0402 1914.37,378.94 r180 top value=1uF
C106 "" C0402 1080.71,362.2 r270 top value=22nF
C107 "" C0402 1739.17,349.41 r90 top value=100nF
C108 "" C0402 1787.4,349.41 r90 top value=1uF
C109 "" C0402 1822.83,349.41 r90 top value=1uF
C110 "" C0603 1635.83,335.63 r90 top value=1uF
C111 "" C0603 1930.12,334.65 r180 top value=10uF
C112 "" C0402 3559.06,234.25 r90 top value=1uF
C113 "" C0402 1080.71,228.35 r270 top value=22nF
C114 "" C0402 994.09,216.54 r90 top value=10nF
C115 "Capacitor" C0402 1555.12,174.21 r90 top value=10nF
C117 "Capacitor" C0402 3305.12,2345.47 r0 bottom value=100nF
C118 "Capacitor" C1206_H1P6 3250,2284.45 r0 bottom value=220uF
C123 "Capacitor" C0402 3305.12,2223.43 r0 bottom value=100nF
C124 "Capacitor" C1206_H1P6 3250,2162.4 r0 bottom value=220uF
C133 "Capacitor" C1206_H1P6 3250,1757.87 r0 bottom value=220uF
C136 "Capacitor" C0402 3305.12,1696.85 r0 bottom value=100nF
C137 "Capacitor" C0402 3305.12,1661.42 r0 bottom value=100nF
C138 "Capacitor" C1206_H1P6 3250,1600.39 r0 bottom value=220uF
C140 "" C0402 2980.31,1278.54 r270 bottom value=100nF
C141 "" C0402 2910.43,1260.83 r270 bottom value=100nF
C142 "" C0402 2772.64,1260.83 r270 bottom value=100nF
C151 "" C0603 894.68,1195.87 r180 bottom value=22uF
C154 "" C0402 2632.87,1199.8 r0 bottom value=100nF
C157 "" C0402 884.84,1151.57 r180 bottom value=100nF
C160 "" C0402 3010.83,1121.06 r180 bottom value=100nF
C164 "" C0402 2632.87,1101.38 r0 bottom value=100nF
C166 "Capacitor" C0805 3843.5,1018.7 r270 bottom value=10uF
C167 "Capacitor" C0402 3790.35,1002.95 r270 bottom value=100pF
C168 "" C0402 3010.83,1002.95 r180 bottom value=100nF
C169 "" C0402 2969.49,882.87 r90 bottom value=100nF
C170 "" C0402 2867.13,882.87 r90 bottom value=100nF
C171 "" C0402 2831.69,882.87 r90 bottom value=100nF
C172 "" C0402 2752.95,882.87 r90 bottom value=100nF
C173 "" C0603 1098.43,820.87 r270 bottom value=22uF
C174 "" C0402 1213.58,808.07 r270 bottom value=100nF
C175 "" C0402 1178.15,808.07 r270 bottom value=100nF
C176 "" C0402 1142.72,808.07 r270 bottom value=100nF
C177 "" C0402 1229.33,711.61 r90 bottom value=100nF
C178 "" C0402 1193.9,711.61 r90 bottom value=100nF
C179 "" C0402 1158.46,711.61 r90 bottom value=100nF
C180 "" C0603 1114.17,698.82 r90 bottom value=22uF
C181 "" C0402 2942.91,678.15 r180 bottom value=100nF
C182 "" C0402 2608.27,560.04 r0 bottom value=100nF
C183 "" C0402 468.5,671.26 r0 bottom value=100nF
C184 "" C0402 2608.27,520.67 r0 bottom value=100nF
C185 "" C0603 3242.13,466.54 r180 bottom value=1uF
C186 "" C0402 2883.86,402.56 r270 bottom value=100nF
C187 "" C0402 3126.97,402.56 r90 bottom value=100nF
C188 "" C0402 3126.97,315.94 r270 bottom value=100nF
C189 "" C0402 3254.92,260.83 r180 bottom value=10nF
C190 "" C0603 3155.51,251.97 r0 bottom value=1uF
CN1 "USB_DUAL_TYPEA_5600-3081" CON_DUAL-USB-TYPE-A_CONEXCON_5600-3081 4055.12,2440.94 r90 top locked value="Dual USB Type A"
CN2 "" CON_SAMTEC_TSW-120-07-G-D 2027.56,2657.48 r0 top locked value="Header 20x2"
CN3 "" CON_MOLEX_53047-0210 1852.36,1141.73 r180 top locked value=53047-0210
CN4 "" CON_TE-CONNECTIVITY_2-1734248-0 885.83,1633.86 r270 top locked value=2-1734248-0
CN5 "USB_DUAL_TYPEA_5600-3081" CON_DUAL-USB-TYPE-A_CONEXCON_5600-3081 4055.12,1732.28 r90 top locked value="Dual USB Type A"
CN6 "" CON_USB-TYPEC_COXOC_317JD24BZTF3K3C3 -39.37,1240.16 r270 top locked value=317JD24BZTF3K3C3
CN7 "" CON_USB-TYPEC_COXOC_317JD24BZTF3K3C3 4015.75,1093.5 r90 top locked value=317JD24BZTF3K3C3
CN8 "RJMG20162141BER" RJMG20162141BER 638.78,737.2 r270 top locked
CN9 "" CON_HDMI_FCI-AMPHENOL_10029449-001RLF 4015.75,374.02 r90 top locked value=10029449-001RLF
CN10 "" CON_JACK-3P5-SMT_LUMBERG_1503-13-VP3 1318.9,-102.36 r90 top locked value="1503 13 VP3"
CN11 "" CON_USBMICROB_MOLEX_105017-0001_H2P90 2972.44,0 r0 top locked value=USB_uB_105017-0001
CN12 "" CON_SAMTEC_TSW-104-07-G-S 3366.14,60.04 r0 top locked value="Header 4x1"
CN13 "" CON_SAMTEC_SSW-110-22-X-S-VS 2339.92,2419.29 r180 bottom locked value="Socket 10x1"
CN14 "" CON_SAMTEC_SSW-108-22-X-S-VS 1379.92,2419.29 r180 bottom locked value="Socket 8x1"
CN15 "DM3BT-DSF-PEJS" DM3BT-DSF-PEJS 348.43,1782.48 r90 bottom
CN16 "" CON_SAMTEC_SSW-108-22-X-S-VS 2079.92,519.29 r0 bottom locked value="Socket 8x1"
CN17 "" CON_SAMTEC_SSW-106-22-X-S-VS 1279.92,519.29 r0 bottom locked value="Socket 6x1"
CN95 "0402" MHDR1X2 1712.6,2185.04 r90 top locked
D1 "" DIO_SOD323 3329.72,436.02 r90 bottom value=BAT60JFILM
D2 "" DIO_SOD323 3008.86,467.52 r0 bottom value=BAT60JFILM
F1 "​f" R0805 3478.35,233.27 r0 top value=picoSMDC035S
H1 "" PTH_M1261-3005-N_3P5X6_M3_H14 885.83,2657.48 r0 top locked
H2 "" PTH_M1261-3005-N_3P5X6_M3_H14 3169.29,2657.48 r0 top locked
H3 "" PTH_M1261-3005-N_3P5X6_M3_H14 885.83,728.35 r0 top locked
H4 "" PTH_M1261-3005-N_3P5X6_M3_H14 3169.29,728.35 r0 top locked
L1 "Inductor" IND_0402_MURATA_LQW15AN2N4C00X 117.13,2450.79 r90 top value=LQW15AN2N4C00x
L4 "Inductor" L0603 329.72,1961.61 r270 top value=LQM18PN2R2MGH
L7 "BEAD" L0603 1066.93,1816.93 r180 top value=30R@100MHz
L8 "BEAD" FIL_0603_H0P65 3003.94,1746.06 r0 top value=26ohm
L10 "" FIL_0603_H0P65 1281.5,734.25 r0 top value=100R@100MHz
L11 "" FIL_0603_H0P65 1035.43,1157.48 r0 bottom value=100R@100MHz
LD1 "LED_red" LED_0603_RED 2406.5,1773.62 r270 top value=RED
LD2 "" LED_0603_GREEN 322.83,1465.55 r180 top value=GREEN
LD3 "" LED_0603_GREEN 453.74,996.06 r180 top value=GREEN
LD4 "" LED_BI-GR_HSMF-A201-A00J1 3213.58,340.55 r0 top value=LD_BICOLOR_CMS
LD5 "" LED_0603_GREEN 1862.2,197.83 r270 top value=GREEN
LD6 "" LED_0603_RED 2179.13,197.83 r270 top value=RED
LD7 "LED_orange" LED_0603_ORANGE_H0P4 2512.8,197.83 r270 top value=ORANGE
LD8 "​reference from jiubaba" LED_0603_SMD-B_BLUE_H0P4 2677.17,190.94 r270 top value=BLUE
LD9 "" LED_0603_GREEN 2735.24,2223.43 r180 bottom value=GREEN
LE1 "" L1210_LQH 865.16,1062.99 r180 bottom value="4.7uH 1A 180R"
Q1 "BCM857BS" DIO_SOT363 515.75,1439.96 r90 top value=BCM857BS7F
Q2 "" MOS_POWERFLAT_3P3X3P3_P065 655.51,1410.43 r180 top value=STL9P3LLH6
R1 "" R0402 2324.8,2515.75 r90 top value=1K5
R2 "" R0402 2366.14,2515.75 r90 top value=1K5
R4 "" R0402 2589.92,2351.81 r90 top value=0R
R5 "" R0402 1611.61,2421.26 r90 top value=1K5
R7 "" R0402 1556.89,2421.85 r90 top value=1K5
R8 "Resistor" R0402 117.13,2217.52 r270 top value=0R
R9 "" R0402 1830.71,2204.72 r270 top value=0R
R10 "Resistor" R0402 117.13,2070.87 r270 top value=0R
R11 "" R0402 995.08,2064.96 r270 top value=10K
R12 "Resistor" R0402 1785.43,2204.72 r90 top value=47K
R13 "" R0402 614.17,2056.1 r180 top value=0R
R14 "" R0402 614.17,1975.39 r180 top value=47K
R16 "" R0402 614.17,1932.09 r180 top value=47K
R17 "Resistor" R0402 411.43,1870.08 r180 top value=47K
R18 "Resistor" R0402 2463.58,1856.3 r180 top value=10K
R19 "" R0402 614.17,1845.47 r180 top value=10K
R20 "Resistor" R0402 411.43,1822.83 r180 top value=47K
R21 "Resistor" R0402 2463.58,1814.96 r0 top value=1K
R22 "Resistor" R0402 411.43,1775.59 r180 top value=47K
R23 "Resistor" R0402 2463.58,1773.62 r0 top value=100K
R24 "Resistor" R0402 2741.14,1752.95 r90 top value=12K
R25 "" R0402 614.17,1758.86 r180 top value=47K
R26 "Resistor" R0402 329.73,1728.35 r180 top value=47K
R27 "Resistor" R0402 411.43,1728.35 r180 top value=47K
R28 "" R0402 614.17,1715.55 r180 top value=47K
R29 "Resistor" R0402 2615.16,1677.17 r90 top value=0R
R30 "Resistor" R0402 2656.5,1677.17 r90 top value=0R
R31 "Resistor" R0402 2973.43,1660.43 r270 top value=0R
R32 "Resistor" R0402 3014.76,1660.43 r90 top value=0R
R33 "" R0402 614.17,1672.24 r180 top value=47K
R34 "Resistor" R0402 3129.92,1589.57 r180 top value=0R
R35 "Resistor" R0402 2964.57,1587.6 r0 top value=0R
R36 "Resistor" R0402 2890.75,1561.02 r270 top value=0R
R39 "Resistor" R0402 413.39,1513.78 r0 top value=47K
R40 "Resistor" R0402 2421.26,1469.49 r270 top value=10K
R41 "" R0402 413.39,1465.55 r0 top value=330R
R42 "Resistor" R0402 3231.3,1394.69 r0 top value=10K
R43 "Resistor" R0402 3141.73,1394.68 r180 top value=1K
R45 "Resistor" R0402 485.24,1365.16 r180 top value=47K
R46 "Resistor" R0402 2937.99,1349.41 r0 top value=0R
R47 "" R0603 569.88,1299.21 r0 top value=0R_0603_ULO
R48 "Resistor" R0402 697.83,1222.44 r270 top value=5K1
R49 "Resistor" R0402 751.97,1204.72 r0 top value=47K
R50 "" R0402 1136.81,1179.13 r270 top value=4K7
R51 "" R0402 1203.74,1179.13 r270 top value=4K7
R52 "" R0402 1270.67,1179.13 r90 top value=4K7
R53 "" R0402 1336.61,1179.13 r90 top value=4K7
R54 "" R0402 1404.53,1179.13 r270 top value=4K7
R55 "" R0402 1472.44,1179.13 r90 top value=4K7
R56 "Resistor" R0402 751.97,1153.54 r0 top value=47K
R57 "Resistor" R0402 697.83,1135.83 r90 top value=5K1
R58 "" R0402 1136.81,1112.2 r270 top value=0R
R59 "" R0402 1203.74,1112.2 r270 top value=0R
R60 "" R0402 1270.67,1112.2 r270 top value=22R
R61 "" R0402 1337.6,1111.22 r270 top value=22R
R62 "" R0402 1404.53,1111.22 r270 top value=22R
R63 "" R0402 1472.44,1111.22 r270 top value=22R
R64 "" R0402 831.69,1018.7 r0 top value=0R
R65 "" R0402 1000,996.06 r180 top value=1K5
R66 "" R0402 375,978.35 r90 top value=510R
R67 "" R0402 531.5,978.35 r90 top value=4K7
R68 "" R0402 831.69,973.43 r0 top value=0R
R69 "" R0402 920.28,932.09 r0 top value=22R
R70 "" R0402 3062.99,888.78 r270 top value=5K1
R71 "" R0402 1759.84,1220.47 r270 bottom value=0R
R72 "" R0402 2755.91,792.91 r180 top value=0R
R75 "" R0402 1319.88,834.65 r270 top value=1K5
R76 "" R0402 1362.2,834.65 r270 top value=1K5
R77 "" R0402 2539.37,836.61 r180 top value=0R
R78 "" R0402 1877.95,1407.48 r90 top value=0R
R79 "" R0402 1860.39,1476.38 r270 top value=0R
R80 "" R0402 2539.37,795.28 r0 top value=10K
R81 "" R0402 2539.37,753.94 r180 top value=10K
R82 "Resistor" R0402 2072.83,690.94 r90 top value=1K
R83 "" R0603 2000.98,580.71 r90 top value=0R
R84 "" R0402 1914.37,600.39 r180 top value=10K
R85 "" R0402 1561.02,575.79 r90 top value=0R
R86 "" R0402 1602.36,575.79 r90 top value=0R
R87 "" R0402 1573.82,514.76 r180 top value=10K
R88 "" R0402 2998.03,494.09 r270 top value=100R
R89 "" R0402 3184.06,474.41 r90 top value=330R
R90 "" R0402 3243.11,474.41 r90 top value=330R
R91 "" R0402 2539.37,471.46 r0 top value=4K7
R92 "" R0402 1080.71,429.13 r270 top value=51R
R93 "" R0402 2998.03,427.17 r270 top value=1K5
R94 "" R0402 2539.37,430.12 r0 top value=4K7
R95 "" R0402 1914.37,417.32 r180 top value=2K2
R96 "" R0402 1968.5,394.69 r270 top value=10K
R97 "" R0402 3304.13,386.81 r270 top value=2K2
R98 "" R0402 3345.47,386.81 r270 top value=2K2
R99 "" R0402 2878.94,345.47 r180 top value=10K
R100 "" R0402 3052.17,345.47 r180 top value=100K
R101 "" R0402 2281.5,313.98 r0 top value=1K
R102 "" R0402 2352.36,313.98 r180 top value=1K
R103 "" R0402 1080.71,295.28 r270 top value=51R
R104 "" R0402 2776.57,287.4 r90 top value=100R
R105 "" R0402 1862.2,284.45 r90 top value=330R
R106 "" R0402 2179.13,284.45 r90 top value=1K
R107 "Resistor" R0402 2512.8,284.45 r270 top value=680R
R108 "Resistor" R0402 2677.17,284.45 r270 top value=680R
R109 "" R0402 1588.58,282.48 r90 top value=10K
R110 "" R0402 1906.5,256.89 r90 top value=100R
R111 "" R0402 2223.43,256.89 r90 top value=100R
R112 "" R0402 2776.57,216.54 r90 top value=36K
R114 "" R0402 2809.06,2241.14 r90 bottom value=510R
R119 "" R0402 2505.91,2234.25 r270 bottom value=100K
R120 "" R0402 2451.77,2216.54 r0 bottom value=47K
R127 "Resistor" R0402 2512.8,2039.37 r90 bottom value=100K
R129 "Resistor" R0402 2440.94,2021.65 r0 bottom value=100K
R134 "Resistor" R0402 2512.8,1936.02 r90 bottom value=100K
R137 "Resistor" R0402 2440.94,1921.26 r0 bottom value=100K
R139 "Resistor" R0402 2526.57,1879.92 r180 bottom value=100K
R140 "Resistor" R0402 2440.94,1879.92 r180 bottom value=100K
R149 "" R0402 3017.72,1209.65 r90 bottom value=4K7
R150 "Resistor" R0603 3906.5,1012.8 r90 bottom value=0R_0603_ULO
R151 "" R0603 1180.12,1032.48 r180 bottom value=0R
R152 "" R0402 2937.01,950.79 r90 bottom value=0R
R153 "" R0402 1051.18,921.26 r270 bottom value=22R
R154 "" R0402 2693.9,882.87 r270 bottom value=0R
R155 "" R0402 1051.18,851.38 r90 bottom value=2K49
R156 "" R0402 41.34,865.16 r270 bottom value=4K7
R157 "" R0402 190.94,853.35 r90 bottom value=510R
R158 "" R0402 2874.02,737.2 r0 bottom value=0R
R159 "" R0402 2726.38,737.2 r0 bottom value=100K
R160 "" R0603 1060.04,698.82 r90 bottom value=0R
R161 "" R0402 2694.88,542.32 r270 bottom value=100K
R162 "" R0402 64.96,730.31 r0 bottom value=510R
R163 "" R0402 188.98,711.61 r90 bottom value=4K7
R164 "Resistor" R0402 3469.49,269.69 r0 bottom value=10K
R165 "" R0402 2051.18,379.92 r180 bottom value=0R
R166 "" R0402 1482.28,314.96 r90 bottom value=1K5
R167 "" R0402 1285.43,314.96 r90 bottom value=1K5
R201 "" R0402 1899.61,1316.93 r0 top value=10K
R300 "Resistor" R0402 1297.24,784.45 r180 top value=10K
R600 "Resistor" R0402 2362.45,1862.2 r270 top value=10K
SB1 "" SOLDER-BRIDGE_R0603-0R 1563.98,712.6 r90 top
SB2 "" SOLDER-BRIDGE_R0603-0R 1619.09,712.6 r90 top
SB3 "" SOLDER-BRIDGE_R0603-0R 1674.21,712.6 r90 top
SB4 "" SOLDER-BRIDGE_R0603-0R 1729.33,712.6 r90 top
SB5 "" SOLDER-BRIDGE_R0603-0R 1927.17,712.6 r270 top
SB6 "" SOLDER-BRIDGE_R0603-0R 2410.43,2264.76 r0 bottom
SB7 "SB_OFF" SOLDER-BRIDGE_R0603-0R 2592.52,2021.65 r180 bottom
SB8 "SB_OFF" SOLDER-BRIDGE_R0603-0R 2592.52,1952.76 r180 bottom
SB13 "" SOLDER-BRIDGE_R0603-0R 1729.33,712.6 r90 bottom
SB14 "" SOLDER-BRIDGE_R0603-0R 1674.21,712.6 r90 bottom
SB15 "" SOLDER-BRIDGE_R0603-0R 1619.09,712.6 r90 bottom
SB16 "" SOLDER-BRIDGE_R0603-0R 1563.98,712.6 r90 bottom
SB17 "" SOLDER-BRIDGE_R0603-0R 2629.92,664.37 r180 bottom
SB18 "" SOLDER-BRIDGE_R0603-0R 2629.92,605.31 r0 bottom
SB19 "" SOLDER-BRIDGE_R0603-0R 2834.65,532.48 r180 bottom
SB20 "" SOLDER-BRIDGE_R0603-0R 2629.92,471.46 r180 bottom
SB21 "" SOLDER-BRIDGE_R0603-0R 3136.81,467.52 r0 bottom
SB22 "" SOLDER-BRIDGE_R0603-0R 2629.92,398.62 r180 bottom
SB23 "SB_ON" SOLDER-BRIDGE_R0603-0R 1434.06,336.61 r270 bottom
SB24 "" SOLDER-BRIDGE_R0603-0R 1378.94,336.61 r270 bottom
SB25 "SB_ON" SOLDER-BRIDGE_R0603-0R 1237.2,336.61 r270 bottom
SB26 "" SOLDER-BRIDGE_R0603-0R 1182.09,336.61 r270 bottom
SW1 "SWITCH_2WAY" SWI_C&K_SDA02H1SBD_2POS 3798.23,382.87 r0 bottom
T1 "" MOS_POWERFLAT_3P3X3P3_P065 3261.81,1274.61 r180 top value=STL9P3LLH6
T2 "" MOS_POWERFLAT_3P3X3P3_P065 3438.98,1274.61 r180 top value=STL9P3LLH6
T3 "" NPN_SOT23 2776.57,247.05 r0 bottom value=9013-SOT23
T4 "" NPN_SOT23 2603.35,2223.43 r90 bottom value=9013-SOT23
TP1 "Test Point" TP_SMD_1MM#1 2477.36,2477.36 r90 top
TP2 "Test Point" TP_SMD_1MM#1 1401.28,1836.68 r180 top value=1mm
TP3 "Test Point" TP_SMD_1MM#1 1401.77,1770.28 r180 top value=1mm
TP4 "Test Point" TP_SMD_1MM#1 1334.84,1703.35 r180 top value=1mm
TP5 "Test Point" TP_SMD_1MM#1 1401.77,1703.35 r180 top value=1mm
TP6 "Test Point" TP_SMD_1MM#1 97.45,1655.51 r90 top value=1mm
TP7 "Test Point" TP_SMD_1MM#1 172.25,1655.51 r90 top value=1mm
TP8 "Test Point" TP_SMD_1MM#1 1334.84,1635.43 r180 top value=1mm
TP9 "Test Point" TP_SMD_1MM#1 1401.77,1635.43 r180 top value=1mm
TP11 "Test Point" TP_SMD_1MM#1 97.44,1580.71 r90 top value=1mm
TP12 "Test Point" TP_SMD_1MM#1 172.24,1580.71 r90 top value=1mm
TP15 "Test Point" TP_SMD_1MM#1 2851.57,1451.38 r90 top value=1mm
TP16 "Test Point" TP_SMD_1MM#1 2875.98,1392.72 r90 top value=1mm
TP17 "Test Point" TP_SMD_1MM#1 3010.83,1325.79 r90 top value=1mm
TP18 "Test Point" TP_SMD_1MM#1 3075.79,1287.4 r90 top value=1mm
TP19 "0402" TP 1441.73,2334.65 r90 top
TP20 "Test Point" TP_SMD_1MM#1 2606.3,802.17 r90 top value=1mm
TP21 "Test Point" TP_SMD_1MM#1 2672.24,802.17 r90 top value=1mm
TP23 "Test Point" TP_SMD_1MM#1 2045.81,1275.59 r90 top value=1mm
TP24 "Test Point" TP_SMD_0-6MM 1133.86,1578.74 r0 bottom
TP25 "Test Point" TP_SMD_0-6MM 1594.49,1870.08 r180 top
TP26 "Test Point" TP_SMD_0-6MM 783.46,1516.73 r90 bottom
TP27 "Test Point" TP_SMD_0-6MM 732.28,1440.94 r0 bottom
TP28 "Test Point" TP_SMD_0-6MM 678.15,1440.94 r0 bottom
TP29 "Test Point" TP_SMD_0-6MM 411.42,1340.55 r0 bottom
TP30 "Test Point" TP_SMD_1MM#1 1862.2,1312.99 r90 bottom value=1mm
TP31 "Test Point" TP_SMD_1MM#2 1740.16,1145.67 r90 bottom value=1mm
TP32 "Test Point" TP_SMD_1MM#1 1673.23,1466.54 r270 top value=1mm
TP33 "Test Point" TP_SMD_1MM#1 1970.47,1326.77 r270 bottom value=1mm
TP53 "0402" TP 2106.3,1594.49 r90 top
TP90 "0402" TP 1870.08,1673.23 r90 top
TP91 "0402" TP 1870.08,1712.6 r90 top
TP93 "0402" TP 2106.3,1555.12 r90 top
TP94 "0402" TP 1830.71,1830.71 r90 top
TP95 "0402" TP 1909.45,1830.71 r270 top
TP96 "0402" TP 1830.71,1476.38 r90 top
TP97 "0402" TP 1673.23,1594.49 r90 top
TP98 "0402" TP 1673.23,1633.86 r90 top
TP99 "0402" TP 1673.23,1673.23 r90 top
TP100 "0402" TP 1870.08,1830.71 r90 top
TP101 "0402" TP 1673.23,1555.12 r90 top
TP102 "0402" TP 1673.23,1515.75 r90 top
TP103 "0402" TP 1791.34,1594.49 r90 top
TP104 "0402" TP 1830.71,1594.49 r90 top
TP400 "0402" TP 1791.34,1397.64 r90 top
U1 "​" ESD_QFN-6L_1P7X1P5_P050 3110.24,2462.6 r270 top value=ECMF02-2AMX6
U2 "​" ESD_QFN-6L_1P7X1P5_P050 3110.24,2368.11 r270 top value=ECMF02-2AMX6
U3 "STMPS2252MTR" ICC_SO8_5X4_P127 3200.79,2208.66 r270 top
U6 "​" ESD_QFN-6L_1P7X1P5_P050 3110.24,2029.53 r270 top value=ECMF02-2AMX6
U7 "USB2514B-AEZC" ICC_QFN36-EPAD_6X6_P050 2637.8,1935.04 r90 top
U8 "LBEE5KL1DX-883" MOD_WLAN-BT_MURATA_LBEE5KL1DX-883 179.14,1846.46 r270 top locked
U9 "​" ESD_QFN-6L_1P7X1P5_P050 3110.24,1935.04 r270 top value=ECMF02-2AMX6
U10 "HSP051-4M10" ESD_UQFN-10L_2P5X1_P050 708.66,1823.82 r90 top locked
U11 "STMPS2252MTR" ICC_SO8_5X4_P127 3200.79,1721.46 r270 top
U12 "​Symbol correction needed ?" ICC_QFN24-EPAD_4X4_P050 3009.84,1468.5 r270 top value=STUSB1600
U13 "OSD32MP157C" ICC_BGA324_18X18_OSD32MP157CAC3 1889.76,1732.28 r90 bottom locked
U14 "" ICC_QFN72-EPAD_10X10_P050 2821.85,1071.85 r270 top locked value=SiI9022ACNU
U15 "New schematic symbol : correction 2 diodes instead of one" ESD_SOT23 598.43,1179.13 r90 top value=ESDA25L
U16 "​Footprint needed DFN105P160X60-2N" ESD_QFN1610_2N_1K_2A 484.25,1161.42 r270 top value=ESDA7P120-1U1M
U17 "New schematic symbol : correction 2 diodes instead of one" ESD_SOT23 3413.39,983.27 r180 top value=ESDA25L
U18 "RTL8211F-CG" ICC_QFN40-EPAD_5X5_P040 1153.54,895.67 r90 top locked
U19 "" ICC_LQFP48_7X7_P050 2775.59,569.88 r270 top locked value=STM32F103CBT6
U20 "" ICC_QFN32-EPAD_5X5_P050 1745.08,504.92 r270 top value=CS42L51-CNZ
U21 "" ESD_SOT666 3062.01,476.38 r0 top value=USBLC6-2P6
U22 "" ESD_SOT23-6L 948.82,381.89 r90 top value=ESDA6V1BC6
U23 "​Footprint needed DFN105P160X60-2N" ESD_QFN1610_2N_1K_2A 1071.85,2401.97 r90 top value=ESDA7P120-1U1M
U24 "​Footprint needed DFN105P160X60-2N" ESD_QFN1610_2N_1K_2A 3675.2,2364.17 r0 bottom value=ESDA7P120-1U1M
U25 "​Footprint needed DFN105P160X60-2N" ESD_QFN1610_2N_1K_2A 3675.2,2301.18 r0 bottom value=ESDA7P120-1U1M
U26 "HSP051-4M10" ESD_UQFN-10L_2P5X1_P050 720.47,1823.82 r90 bottom locked
U27 "​Footprint needed DFN105P160X60-2N" ESD_QFN1610_2N_1K_2A 3675.2,1657.48 r0 bottom value=ESDA7P120-1U1M
U28 "​Footprint needed DFN105P160X60-2N" ESD_QFN1610_2N_1K_2A 3675.2,1594.49 r0 bottom value=ESDA7P120-1U1M
U29 "​" ESD_QFN-6L_1P7X1P5_P050 3447.83,1103.35 r90 bottom value=ECMF02-2AMX6
U30 "​Footprint needed DFN105P160X60-2N" ESD_QFN1610_2N_1K_2A 3741.14,1009.84 r90 bottom value=ESDA7P120-1U1M
U31 "" ESD_UQFN-10L_2P60X1P35_P050 3552.17,512.8 r270 bottom value=ECMF04-4HSWM10
U32 "" ESD_UQFN-10L_2P60X1P35_P050 3552.17,391.73 r270 bottom value=ECMF04-4HSWM10
U33 "ESDALC6V1-5M6" ESD_UQFN-6L_1P45X1_P050 3552.17,289.37 r270 bottom
U34 "" REG_SOT23-5L 3218.5,359.25 r0 bottom value=LD3985M33R
U35 "ESD-TRANSIL" ESD_ST0201 1588.58,180.12 r270 top value=ESDALC6V1-1U2
X1 "XTAL_24M_7A-24.000MAAE-T" CRY_TXC_7A-SERIES_5X3P2_H1P2_2P 2635.83,1566.93 r0 top
X2 "XTAL_4_PINS" CRY_NX3225HA_4P 683.07,996.06 r180 top value=25MHz
X4 "" CRY_NX2012SA_2P 1807.09,1232.28 r270 bottom value=32.768kHz
X5 "" CRY_NX3225GD_2P 2504.92,589.57 r90 top value=NX3225GD-8.00M

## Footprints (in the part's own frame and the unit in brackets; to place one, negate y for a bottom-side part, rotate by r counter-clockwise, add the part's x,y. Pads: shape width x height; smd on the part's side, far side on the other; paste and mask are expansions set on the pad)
C0402 [mm]
  rect 0.51x0.56 smd mask+0.05: 1(-0.45,0) 2(0.45,0)
  silkscreen extent -0.72,-0.35 0.72,0.35, body extent -0.5,-0.3 0.5,0.3, height 0.4
C0603 [mm]
  rect 0.64x0.89 smd mask+0.05: 1(-0.7,0) 2(0.7,0)
  silkscreen extent -1.05,-0.55 1.02,0.55, body extent -0.9,-0.5 0.9,0.5, height 1.4
C0805 [mm]
  rect 0.9x1.4 smd mask+0.05: 1(-0.85,0) 2(0.85,0)
  silkscreen extent -1.3,-0.77 1.3,0.77, body extent -1.1,-0.7 1.1,0.7, height 1.35
C1206_H1P6 [mm]
  rect 1.4x1.78 smd mask+0.05: 1(-1.4,0) 2(1.4,0)
  silkscreen extent -2.12,-0.97 2.15,0.97, body extent -1.7,-0.9 1.7,0.9, height 1.8
CON_DUAL-USB-TYPE-A_CONEXCON_5600-3081 [mm]
  round 1.6 hole 0.92: B1(-3.5,13.01) B2(-1,13.01) B3(1,13.01) B4(3.5,13.01) T2(-1,15.63) T3(1,15.63) T4(3.5,15.63)
  round 3.8 hole 2.33: CH1(6.57,10.3) CH2(-6.57,10.3) CH3(-6.57,15.98) CH4(6.57,15.98)
  rect 1.6x1.6 hole 0.92: T1(-3.5,15.63)
  silkscreen extent -7.3,-0.4 7.3,17.85, body extent -7.83,-0.6 7.87,17.85, height 16.2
